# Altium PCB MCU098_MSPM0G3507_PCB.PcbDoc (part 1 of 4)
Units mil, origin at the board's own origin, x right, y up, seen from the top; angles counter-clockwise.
Board outline 2310.03 x 4205.03 mil, 4 copper layers (Top Layer, VCC Layer, GND Layer, Bottom Layer), stack 62.4 mil thick; 260 components, 182 nets, 835 pads, 237 vias.
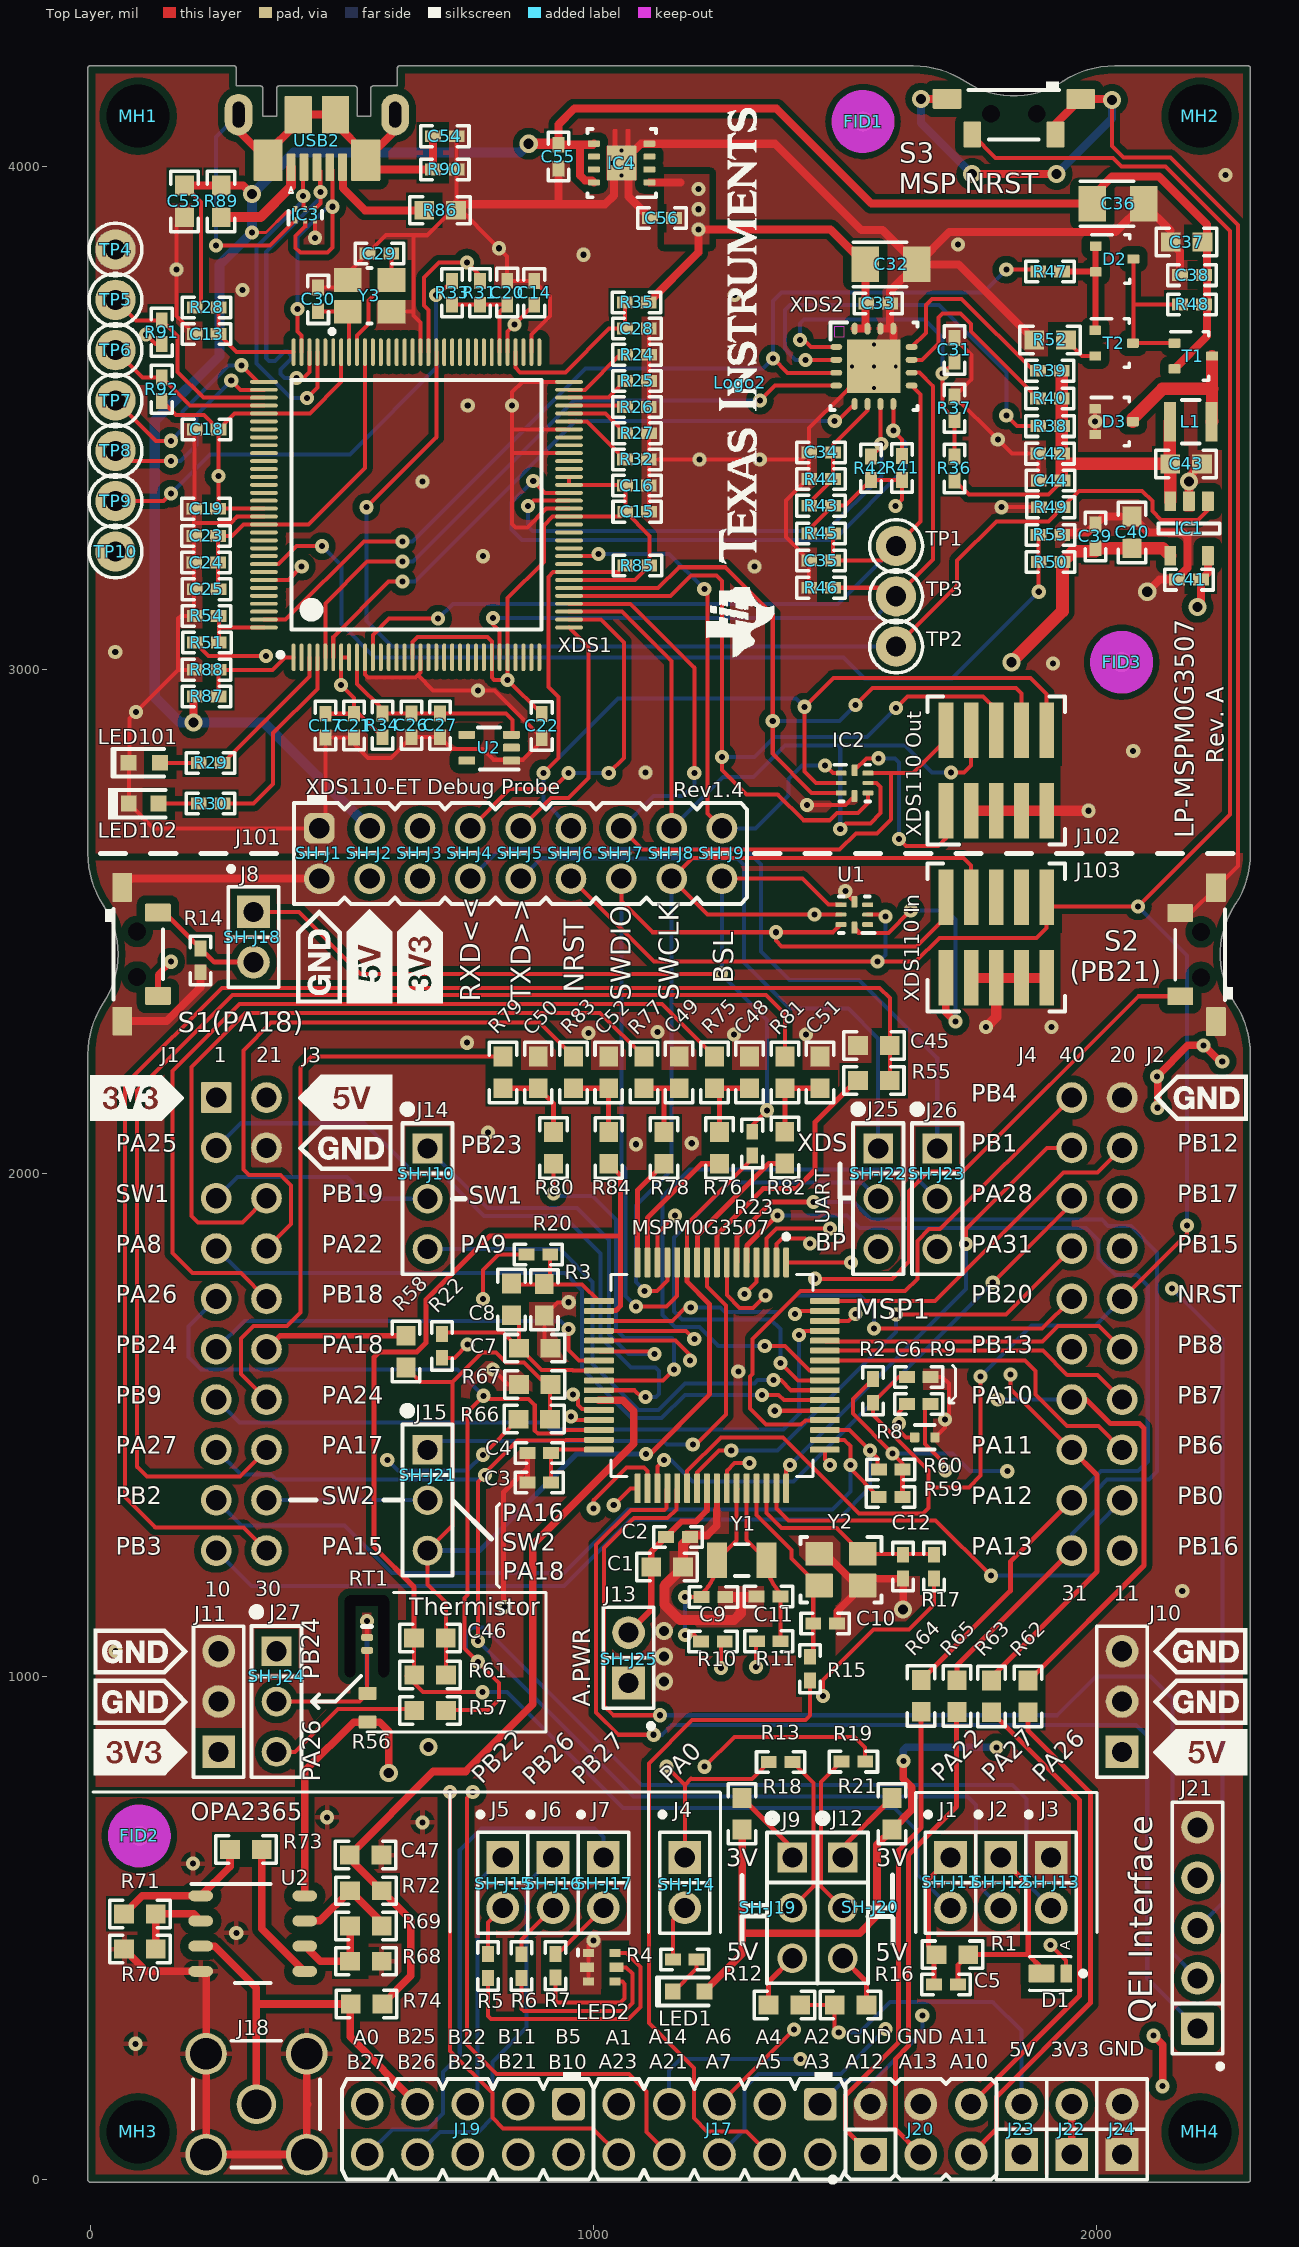
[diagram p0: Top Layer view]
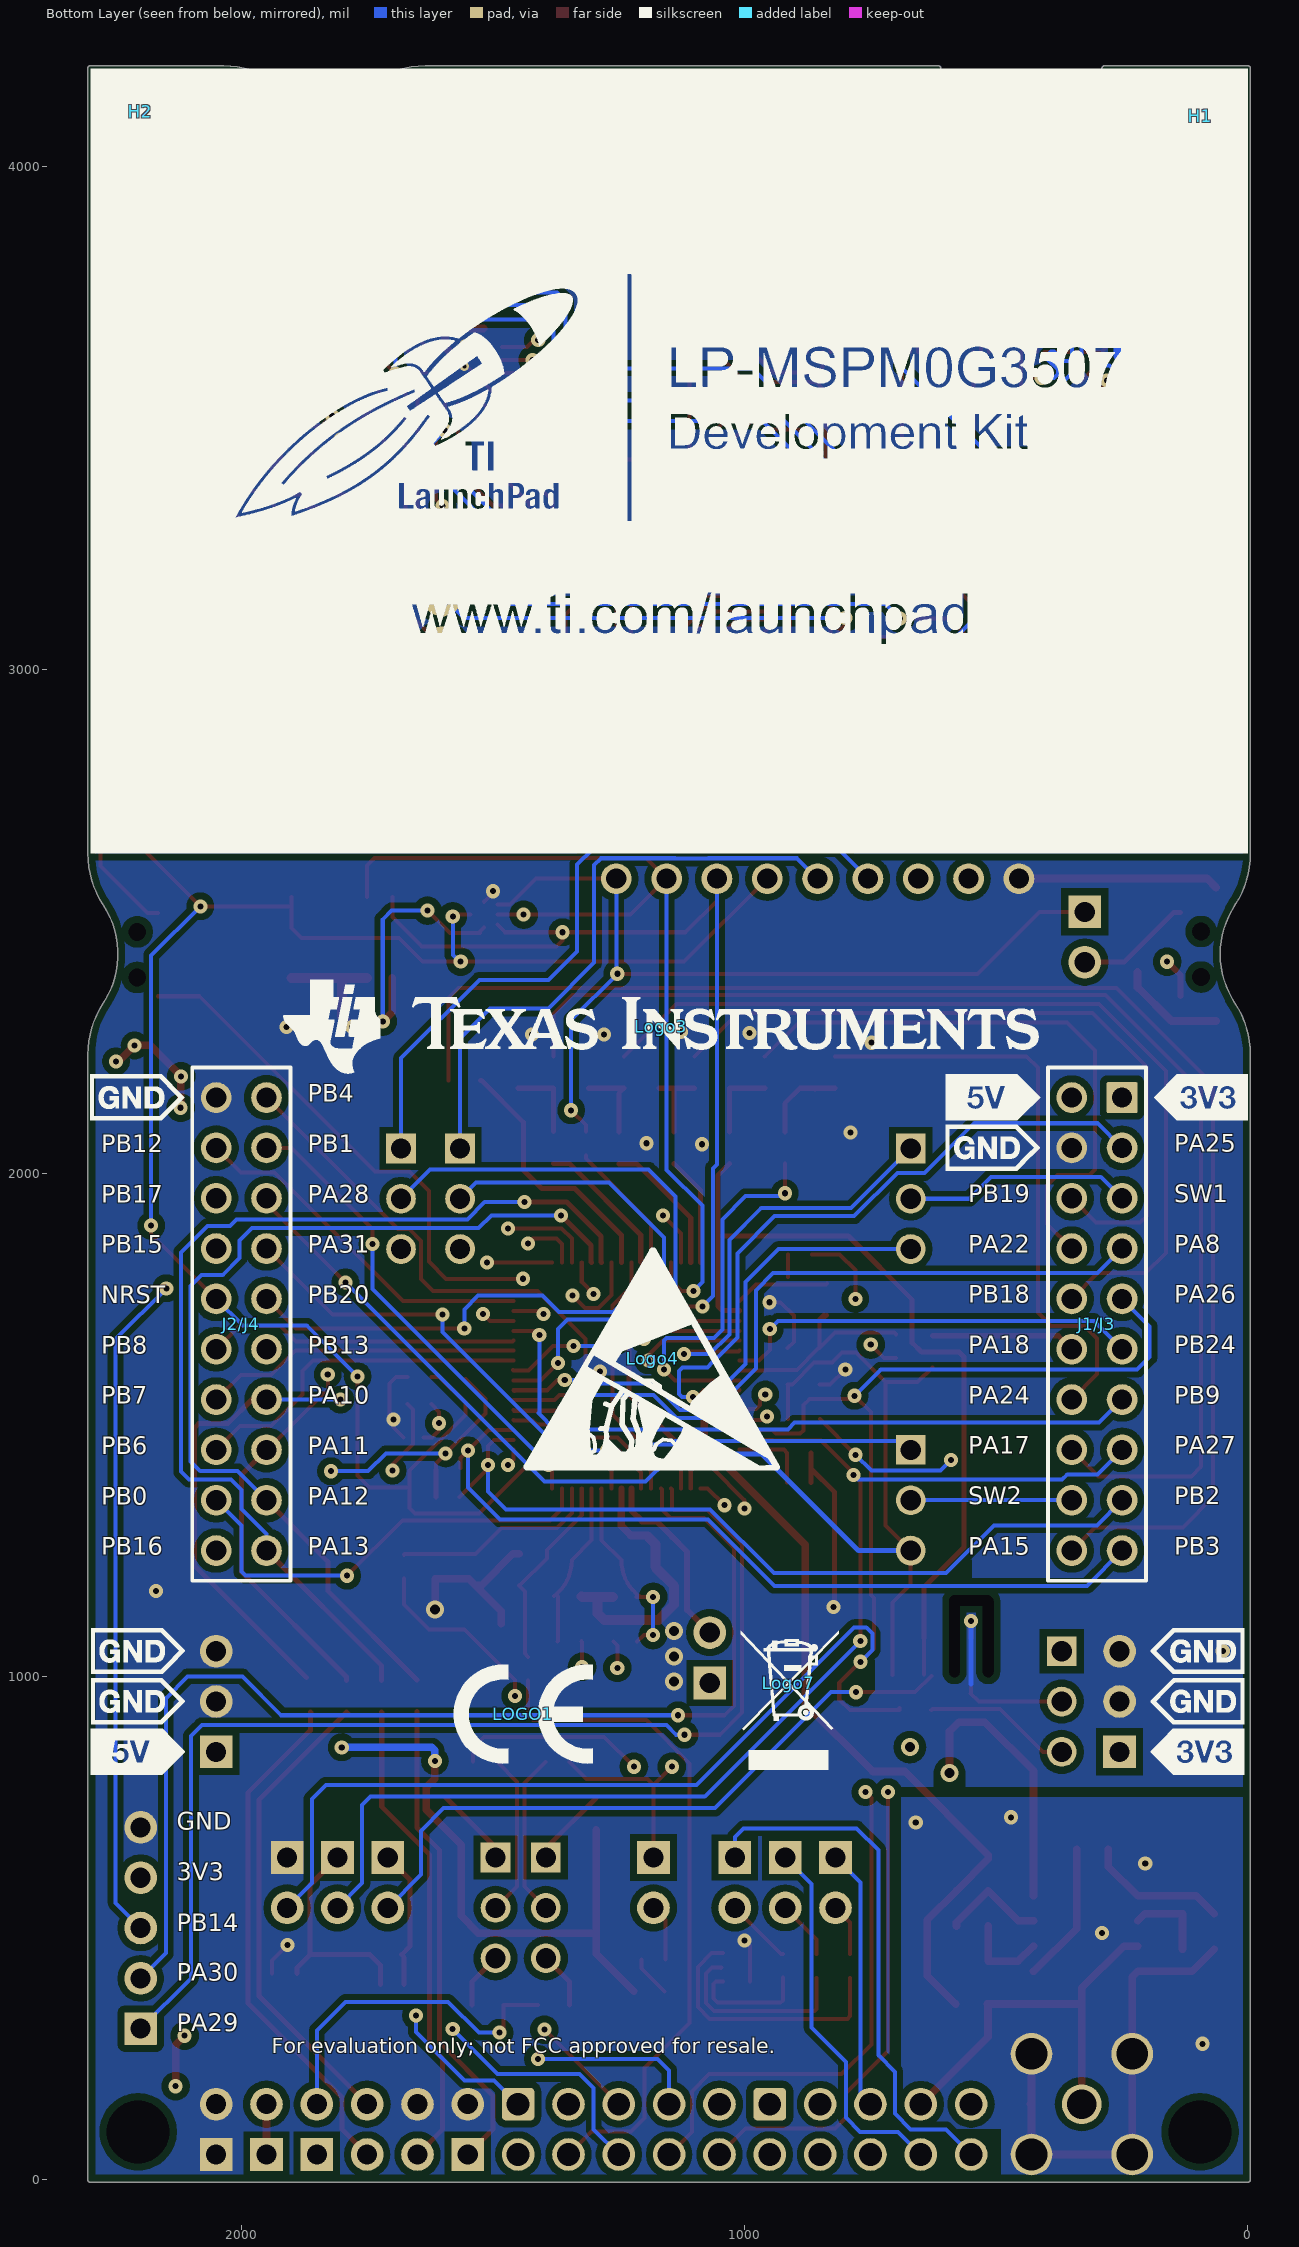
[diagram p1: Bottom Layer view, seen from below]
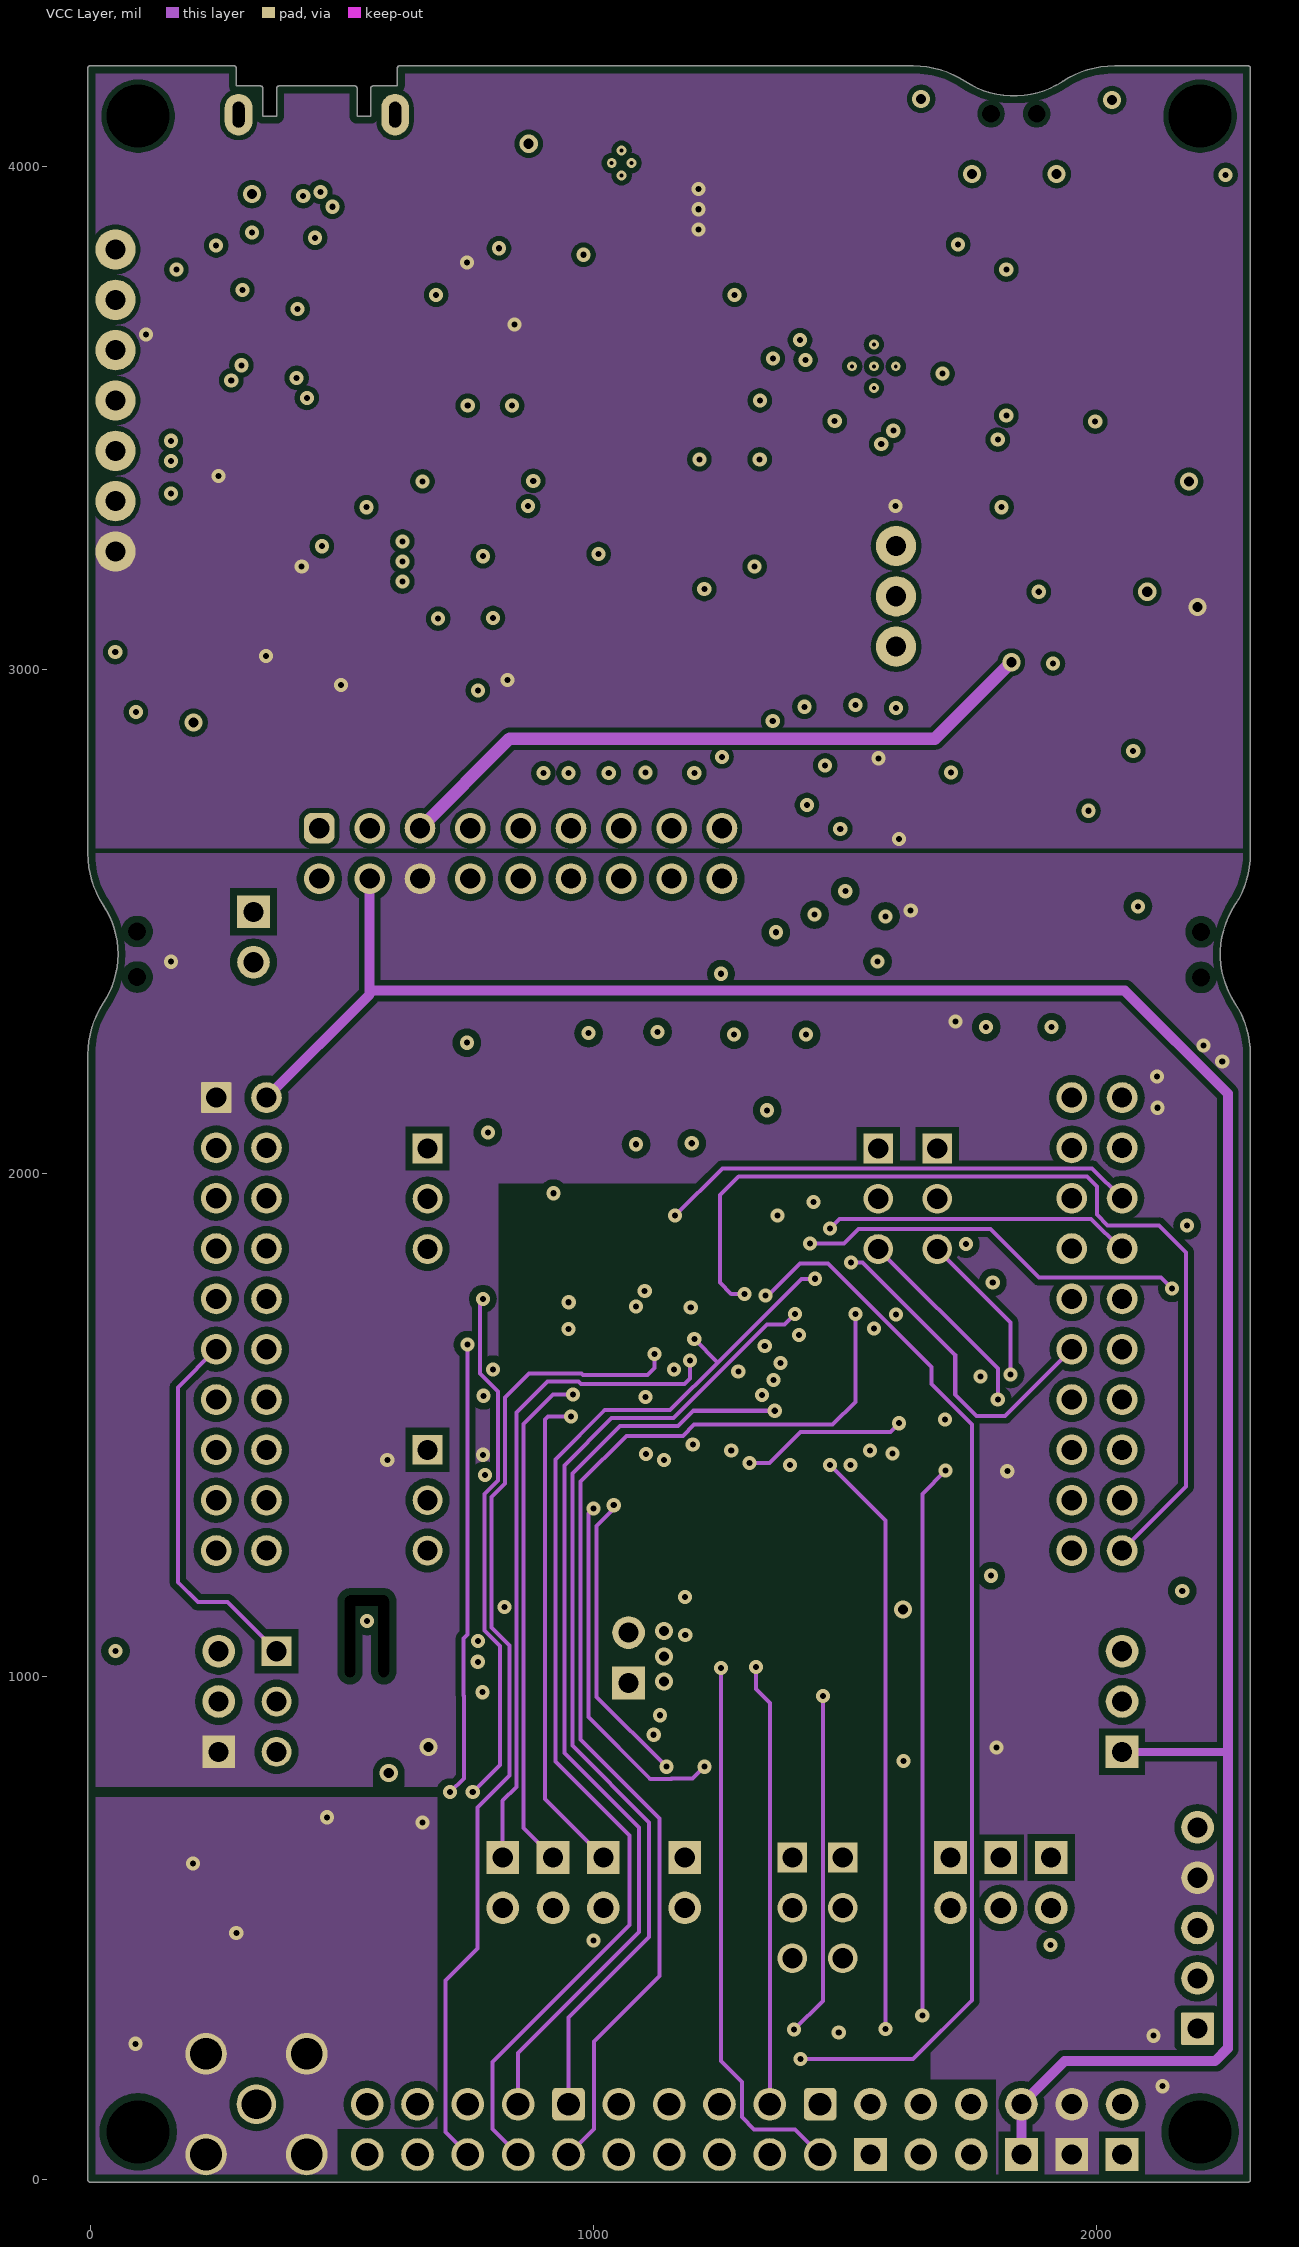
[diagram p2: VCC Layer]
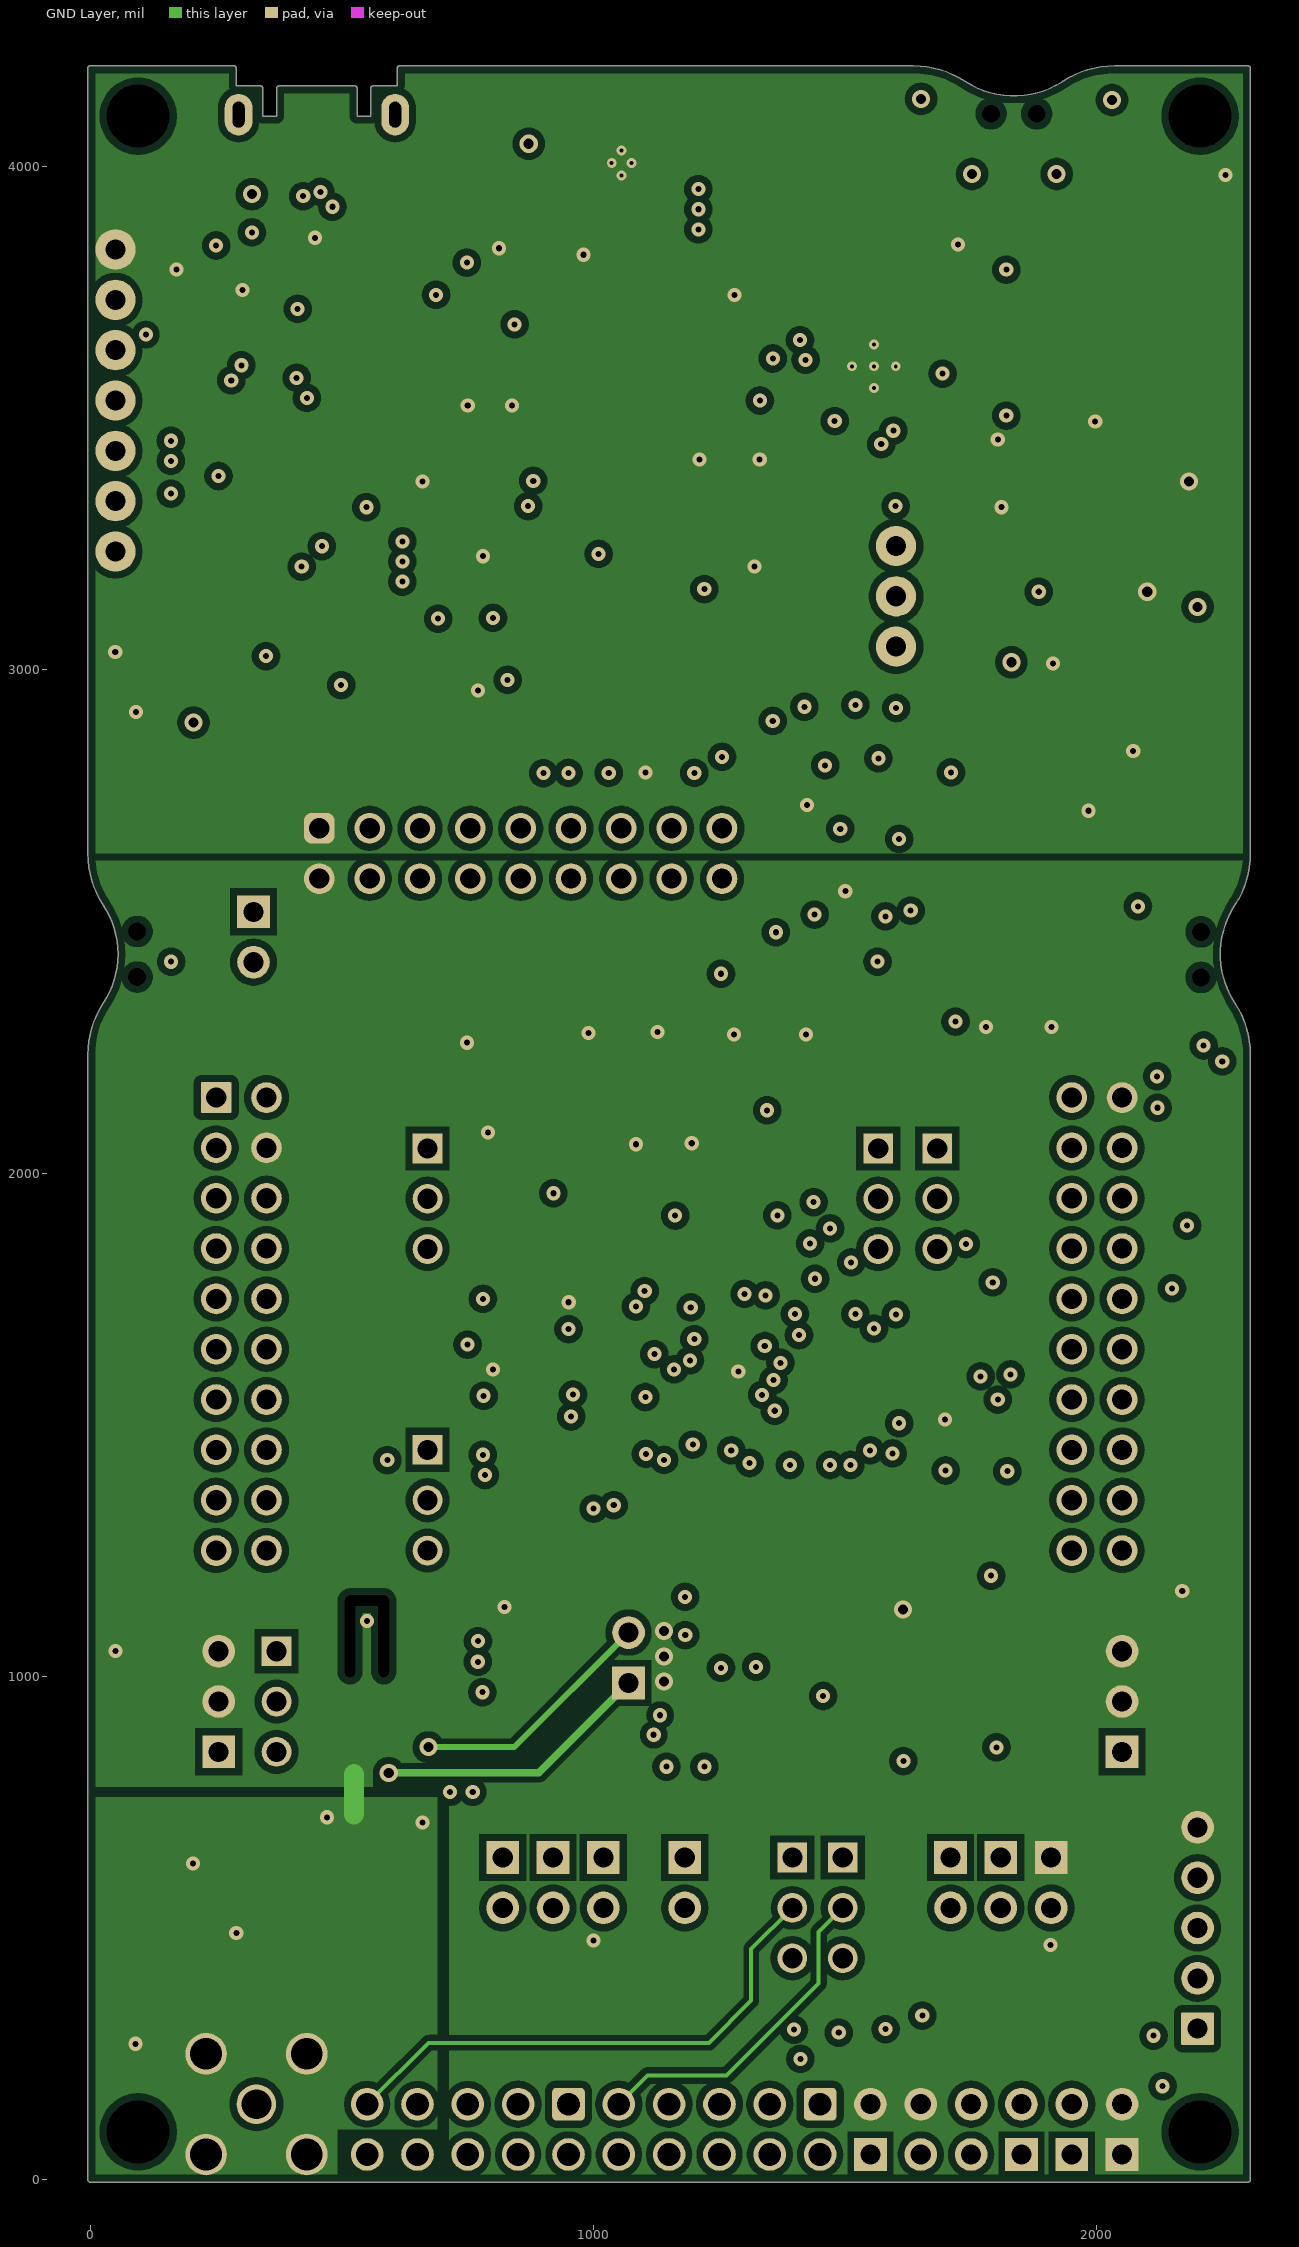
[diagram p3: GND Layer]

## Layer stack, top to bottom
Top Solder: solder mask 0.9843, SM-004, Dk 4
Top Layer: signal copper 1.4
Dielectric 2: core 8.4, FR-4, Dk 4.2
VCC Layer: signal copper 1.4
Dielectric1: prepreg 40, FR-4, Dk 4.2
GND Layer: signal copper 1.4
Dielectric 3: core 8.4, FR-4, Dk 4.2
Bottom Layer: signal copper 1.4
Bottom Solder: solder mask 0.9843, SM-004, Dk 4

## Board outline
-5.01,0 -5.01,2235 cw(c181.67,2235) 25.81,2337.76 ccw(c-121.67,2435) 25.83,2337.79 ccw(c-121.67,2435) 54.99,2435 ccw(c-121.67,2435) 25.88,2532.14 cw(c30,2535) 25.81,2532.24 cw(c181.67,2635) -5.01,2635 -5.01,4195 cw(c0,4195) 0,4200.02 285,4200.02 cw(c285,4195) 290.02,4195 290.02,4160.02 338,4160.02 cw(c338,4155) 343.02,4155 343.02,4100.02 369.99,4100.02 369.99,4155 cw(c375,4155) 375,4160.02 525,4160.02 cw(c525,4155) 530.02,4155 530.02,4100.02 556.99,4100.02 556.99,4155 cw(c562,4155) 562,4160.02 609.99,4160.02 609.99,4195 cw(c615,4195) 615,4200.02 1635,4200.02 cw(c1635,4013.33) 1737.76,4169.19 ccw(c1835,4316.67) 1737.79,4169.17 ccw(c1835,4316.67) 1932.14,4169.12 ccw(c1835,4316.67) 1932.24,4169.18 1932.24,4169.19 cw(c2035,4013.33) 2035,4200.02 2300,4200.02 cw(c2300,4195) 2305.02,4195 2305.02,2635 cw(c2118.33,2635) 2274.19,2532.24 cw(c2270,2535) 2274.17,2532.21 cw(c2421.67,2435) 2274.19,2532.24 2274.17,2532.21 ccw(c2421.67,2435) 2274.12,2337.86 cw(c2270,2335) 2274.19,2337.76 cw(c2118.33,2235) 2305.02,2235 2305.02,0.03 cw(c2300,0) 2305.02,0 2305.02,2235 2305.02,0.03 2305.02,0 cw(c2300,0) 2300,-5.01 0,-5.01 cw(c0,0)

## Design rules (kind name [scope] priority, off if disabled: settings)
AcuteAngle [All] p1: minimum=4.50000000000000E+0001 checktracksonly=FALSE
AssemblyTestPointUsage [All] p1: valid=2
BoardOutlineClearance BoardOutlineClearance_MountingHoles [OnCopper and InComponentClass('Mounting Holes')] p1: gap=15 ignorepadtopadclearanceinfootprint=FALSE
BoardOutlineClearance BoardOutlineClearance_Poly [OnCopper and IsPoly] p2: gap=15 ignorepadtopadclearanceinfootprint=FALSE
BoardOutlineClearance [OnCopper and Not InComponentClass('Logo') and not InComponentClass('FiducialMark') and not InRegion(1000,500,4000,800) and not InPoly] p3: gap=10 ignorepadtopadclearanceinfootprint=FALSE
Clearance SMD [InNamedPolygon('GND_LAYER_GND_P-001')] p1: gap=10 ignorepadtopadclearanceinfootprint=FALSE except(0: Arc-Hole Track-Hole SMDPad-Hole THPad-Hole Via-Hole Fill-Hole Poly-Hole Region-Hole Text-Hole; 20: SMDPad-SMDPad SMDPad-THPad SMDPad-Via SMDPad-Fill SMDPad-Poly SMDPad-Region SMDPad-Text)
Clearance Clearance_FiducialMark [IsKeepOut and InComponentClass('FiducialMark') vs IsPad and InComponentClass('FiducialMark')] p2: gap=0 ignorepadtopadclearanceinfootprint=FALSE
Clearance Clearance_Keepouts [((IsTrack Or IsArc) And Not InPoly) And IsFree and IsKeepOut vs ((IsTrack Or IsArc) And Not InPoly) And IsFree and IsKeepOut] p3: gap=0 ignorepadtopadclearanceinfootprint=FALSE
Clearance Clearance_Poly [InPolygon] p4: gap=14 ignorepadtopadclearanceinfootprint=FALSE except(0: Arc-Hole Track-Hole SMDPad-Hole THPad-Hole Via-Hole Fill-Hole Poly-Hole Region-Hole Text-Hole; 12: Arc-Fill Arc-Poly Arc-Region Track-Fill Track-Poly Track-Region; 15: THPad-THPad; 17: SMDPad-Fill SMDPad-Poly SMDPad-Region)
Clearance [All] p5: gap=6 ignorepadtopadclearanceinfootprint=FALSE
ComponentClearance ComponentClearance_Standoffs [HasFootprint('KY_MAE-10') vs HasFootprint('NPTH125mil')] p1: gap=0 collisioncheckmode=3 verticalgap=0 showdistances=FALSE
ComponentClearance ComponentClearance_2PinHeaders [HasFootprint('TSW-102-07-G-S') vs HasFootprint('TSW-102-07-G-S')] p2: gap=0 collisioncheckmode=3 verticalgap=0 showdistances=FALSE
ComponentClearance ComponentClearance_TestPoint [HasFootprint('Keystone5001') vs HasFootprint('Keystone5001')] p3: gap=0 collisioncheckmode=3 verticalgap=0 showdistances=FALSE
ComponentClearance ComponentClearance_MountingHoles_FiducialMarks [InComponentClass('Mounting Holes') vs InComponentClass('FiducialMark')] p4: gap=0 collisioncheckmode=3 verticalgap=0 showdistances=FALSE
ComponentClearance ComponentClearance_ShuntToShunt [InComponentClass('Shunt') vs InComponentClass('Shunt')] p5: gap=0 collisioncheckmode=3 verticalgap=0 showdistances=FALSE
ComponentClearance ComponentClearance_Shunt [InComponentClass('Header') vs InComponentClass('Shunt')] p6: gap=0 collisioncheckmode=3 verticalgap=0 showdistances=FALSE
ComponentClearance ComponentClearance_Logo [InComponentClass('Logo')] p7: gap=0 collisioncheckmode=3 verticalgap=0 showdistances=FALSE
ComponentClearance ComponentClearance_ScrewToNut [(HasFootprint('NY PMS 440 0025 PH')) vs (HasFootprint('Keystone_1902C'))] p8: gap=5 collisioncheckmode=3 verticalgap=10 showdistances=FALSE
ComponentClearance ComponentClearance_MountingHoles [InComponentClass('Mounting Holes')] p9: gap=250 collisioncheckmode=3 verticalgap=100000 showdistances=FALSE
ComponentClearance ComponentClearance_SmallPassives [HasFootprint('0201*') or HasFootprint('0402*') or HasFootprint('0508') or HasFootprint('0603*') or HasFootprint('0612') or HasFootprint('0805*') or HasFootprint('0815*') or HasFootprint('0830*') or HasFootprint('1206*') or HasFootprint('1210*') or HasFootprint('1808*') or HasFootprint('1812*') or HasFootprint('1825*') or HasFootprint('2010*') or HasFootprint('2220*') or HasFootprint('2225*') or HasFootprint('2512*') or HasFootprint('2728*') or HasFootprint('3518*') vs HasFootprint('0201*') or HasFootprint('0402*') or HasFootprint('0508') or HasFootprint('0603*') or HasFootprint('0612') or HasFootprint('0805*') or HasFootprint('0815*') or HasFootprint('0830*') or HasFootprint('1206*') or HasFootprint('1210*') or HasFootprint('1808*') or HasFootprint('1812*') or HasFootprint('1825*') or HasFootprint('2010*') or HasFootprint('2220*') or HasFootprint('2225*') or HasFootprint('2512*') or HasFootprint('2728*') or HasFootprint('3518*')] p10: gap=0 collisioncheckmode=3 verticalgap=0 showdistances=FALSE
ComponentClearance ComponentClearance_THtoSMT [IsThruComponent vs IsSMTComponent] p11: gap=0 collisioncheckmode=3 verticalgap=0 showdistances=FALSE
ComponentClearance ComponentClearance_THtoTH [IsThruComponent vs IsThruComponent] p12: gap=0 collisioncheckmode=3 verticalgap=0 showdistances=FALSE
ComponentClearance [All] p13: gap=0 collisioncheckmode=3 verticalgap=0 showdistances=FALSE
DiffPairsRouting [All] p1: maxlimit=100 minlimit=10 mostfreqgap=10 toplayer_minwidth=15 toplayer_maxwidth=15 toplayer_prefwidth=15 midlayer1_minwidth=15 midlayer1_maxwidth=15 midlayer1_prefwidth=15 midlayer2_minwidth=15 midlayer2_maxwidth=15 midlayer2_prefwidth=15 bottomlayer_minwidth=15 bottomlayer_maxwidth=15 bottomlayer_prefwidth=15 maxuncoupledlength=1000
FabricationTestPointUsage TestPointUsage [All] p1: valid=2 allowmultiple=FALSE
FabricationTestpoint Testpoint [All] p1: side=3 testpointundercomponent=TRUE minsize=40 maxsize=100 preferedsize=60 minholesize=0 maxholesize=40 preferedholesize=32 testpointgrid=1 allowsidetop=TRUE allowsidebottom=TRUE usegrid=TRUE gridtolerance=0.01
FanoutControl Fanout_LCC [IsLCC] p1: bgadir=Out bgaviamode=Centered fanoutstyle=Auto fanoutdirection=Alternating viagrid=1 // Fanout_LCC (Default Rule)
FanoutControl Fanout_BGA [IsBGA] p2: bgadir=Out bgaviamode=Centered fanoutstyle=Auto fanoutdirection=Alternating viagrid=1 // Fanout_BGA (Default Rule)
FanoutControl Fanout_Default [All] p4: bgadir=Out bgaviamode=Centered fanoutstyle=Auto fanoutdirection=Alternating viagrid=1 // Fanout_Default (Default Rule)
FanoutControl Fanout_Small [(CompPinCount < 5)] p5: bgadir=Out bgaviamode=Centered fanoutstyle=Auto fanoutdirection=OutThenIn viagrid=1 // Fanout_Small (Default Rule)
HoleSize [All] p1: absolutevalues=TRUE maxlimit=251 minlimit=7.87 maxpercent=80.000 minpercent=20.000
MinimumAnnularRing MinimumAnnularRing_ThermalPadVias [IsVia and InAnyComponent] p1: minimumring=5.91
MinimumAnnularRing [All] p2: minimumring=6
MinimumSolderMaskSliver MinimumSolderMaskSliver_Logo [InComponentClass('Logo') vs InComponentClass('Logo')] p1: minsoldermaskwidth=0.7
MinimumSolderMaskSliver [All] p2: minsoldermaskwidth=3.94
PlaneClearance [All] p1: clearance=10
PlaneConnect [All] p1: planeconnectstyle=Relief reliefexpansion=10 reliefentries=4 reliefconductorwidth=10 reliefairgap=10
PolygonConnect PolygonConnect_14 [All vs IsNamedPolygon('GND_LAYER_GND_P-001')] p1: connectstyle=Direct reliefconductorwidth=10 reliefentries=4 polygonreliefangle="90 Angle" airgapwidth=10
PolygonConnect PolygonConnect_13 [All vs IsNamedPolygon('BOTTOM_LAYER_GND_P036')] p2: connectstyle=Direct reliefconductorwidth=10 reliefentries=4 polygonreliefangle="90 Angle" airgapwidth=10
PolygonConnect PolygonConnect_12 [All vs IsNamedPolygon('TOP_LAYER_GND_P034')] p3: connectstyle=Direct reliefconductorwidth=10 reliefentries=4 polygonreliefangle="90 Angle" airgapwidth=10
PolygonConnect PolygonConnect_11 [All vs IsNamedPolygon('VCC_LAYER_3V3_P032')] p4: connectstyle=Direct reliefconductorwidth=10 reliefentries=4 polygonreliefangle="90 Angle" airgapwidth=10
PolygonConnect PolygonConnect_10 [All vs IsNamedPolygon('GND_LAYER_GND_P030')] p5: connectstyle=Direct reliefconductorwidth=10 reliefentries=4 polygonreliefangle="90 Angle" airgapwidth=10
PolygonConnect PolygonConnect_9 [All vs IsNamedPolygon('BOTTOM_LAYER_GND_P028')] p6: connectstyle=Direct reliefconductorwidth=10 reliefentries=4 polygonreliefangle="90 Angle" airgapwidth=10
PolygonConnect PolygonConnect_8 [All vs IsNamedPolygon('GND_LAYER_GND_P026')] p7: connectstyle=Direct reliefconductorwidth=10 reliefentries=4 polygonreliefangle="90 Angle" airgapwidth=10
PolygonConnect PolygonConnect_7 [All vs IsNamedPolygon('VCC_LAYER_GND_P024')] p8: connectstyle=Direct reliefconductorwidth=10 reliefentries=4 polygonreliefangle="90 Angle" airgapwidth=10
PolygonConnect PolygonConnect_6 [All vs IsNamedPolygon('TOP_LAYER_GND_P022')] p9: connectstyle=Relief reliefconductorwidth=10 reliefentries=4 polygonreliefangle="90 Angle" airgapwidth=10
PolygonConnect PolygonConnect_5 [All vs IsNamedPolygon('BOTTOM_LAYER_XDS_GND_P014')] p10: connectstyle=Direct reliefconductorwidth=10 reliefentries=4 polygonreliefangle="90 Angle" airgapwidth=10
PolygonConnect PolygonConnect_4 [All vs IsNamedPolygon('TOP_LAYER_XDS_GND_P010')] p11: connectstyle=Direct reliefconductorwidth=10 reliefentries=4 polygonreliefangle="90 Angle" airgapwidth=10
PolygonConnect PolygonConnect_3 [All vs IsNamedPolygon('GND_LAYER_XDS_GND_P008')] p12: connectstyle=Direct reliefconductorwidth=10 reliefentries=4 polygonreliefangle="90 Angle" airgapwidth=10
PolygonConnect PolygonConnect_2 [All vs IsNamedPolygon('TOP_LAYER_XDS_VCC_P004')] p13: connectstyle=Direct reliefconductorwidth=10 reliefentries=4 polygonreliefangle="90 Angle" airgapwidth=10
RoutingVias ThermalPadVias [IsVia and InAnyComponent] p1: holewidth=7.87 width=19.68 viastyle="Through Hole" minholewidth=7.87 minwidth=19.68 maxholewidth=16 maxwidth=30
RoutingVias [All] p2: holewidth=12 width=28 viastyle="Through Hole" minholewidth=7.87 minwidth=26 maxholewidth=40 maxwidth=65
SilkToBoardRegionClearance [Not ((IsComment or IsDesignator) And (Hide <> 'False')) and not InRegion(1000,500,4000,800)] p1:
SilkToSilkClearance SilkToSilkClearance_Pb-FreeLogo [(HasFootprint('Pb-Free_Overlay_Medium') OR HasFootprint('Pb-Free_Overlay_Small')) vs (HasFootprint('Pb-Free_Overlay_Medium') OR HasFootprint('Pb-Free_Overlay_Small'))] p1: silktosilkclearance=0
SilkToSilkClearance [All] p2: silktosilkclearance=0
SilkToSolderMaskClearance SilkToComponentPadClearance [(IsPad or IsFill or IsRegion) and InAnycomponent] p1: minsilkscreentomaskgap=0 clearancetoexposedcopper=TRUE
SilkToSolderMaskClearance "Silk to Solder Mask Opening" [All] p2: minsilkscreentomaskgap=0 clearancetoexposedcopper=FALSE
SolderMaskExpansion SolderMaskExpansion_via [isvia] p1: expansion=-17
SolderMaskExpansion [All] p2: expansion=1.97
Width [All] p1: maxlimit=100 minlimit=6 preferedwidth=10 checkconnectedcopper=TRUE
14 further rules are at their usual default settings.

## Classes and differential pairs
component class MCU098_07_Hardware: "30N.C. ROUTE" !PCB FID1 FID2 FID3 H1 H2 LOGO1 Logo2 Logo3 Logo4 Logo6 Logo7 MH1 MH2 MH3 MH4 SH-J1 SH-J2 SH-J3 SH-J4 SH-J5 SH-J6 SH-J7 SH-J8 SH-J9 SH-J10 SH-J11 SH-J12 SH-J13 SH-J14 SH-J15 SH-J16 SH-J17 SH-J18 SH-J19 SH-J20 SH-J21 SH-J22 SH-J23 SH-J24 SH-J25 SH-J101A SH-J101B SH-J101C SH-J101D SH-J101E SH-J101F SH-J101G SH-J101H SH-J101I SH-J101J USB1 ZZ1 ZZ2 ZZ3 ZZ4
component class MCU098_06_XDS110-ET_USB_Power: "30N.C. ROUTE" C53 C54 C55 C56 IC3 IC4 R86 R87 R88 R89 R90 R91 R92 TP4 TP5 TP6 TP7 TP8 TP9 TP10 USB2
component class MCU098_05_XDS110_Target_Interface: "30N.C. ROUTE" IC2 J101 J102 J103 R85 U1
component class MCU098_04_XDS110-ET_EnergyTrace: "30N.C. ROUTE" C31 C32 C33 C34 C35 C36 C37 C38 C39 C40 C41 C42 C43 C44 D2 D3 IC1 L1 R36 R37 R38 R39 R40 R41 R42 R43 R44 R45 R46 R47 R48 R49 R50 R51 R52 R53 R54 T1 T2 XDS2
component class MCU098_03_XDS110_Debug_Probe: "30N.C. ROUTE" C13 C14 C15 C16 C17 C18 C19 C20 C21 C22 C23 C24 C25 C26 C27 C28 C29 C30 LED101 LED102 R24 R25 R26 R27 R28 R29 R30 R31 R32 R33 R34 R35 TP1 TP2 TP3 U2 XDS1 Y3
component class MCU098_02_BoosterPack_Connectors: "30N.C. ROUTE" C45 C46 C47 C48 C49 C50 C51 C52 J1/J3 J2/J4 J14 J15 J17 J18 J19 J20 J21 J22 J23 J24 J27 R55 R56 R57 R58 R59 R60 R61 R62 R63 R64 R65 R66 R67 R68 R69 R70 R71 R72 R73 R74 R75 R76 R77 R78 R79 R80 R81 R82 R83 R84 RT1 U2
component class MCU098_01_MSPM0G3507_Target_Device: "30N.C. ROUTE" C1 C2 C3 C4 C5 C6 C7 C8 C9 C10 C11 C12 D1 J1 J2 J3 J4 J5 J6 J7 J8 J9 J10 J11 J12 J13 J25 J26 LED1 LED2 MSP1 R1 R2 R3 R4 R5 R6 R7 R8 R9 R10 R11 R12 R13 R14 R15 R16 R17 R18 R19 R20 R21 R22 R23 S1 S2 S3 Y1 Y2
component class FiducialMark: "30N.C. ROUTE" FID1 FID2 FID3
component class AssemblyNote: "30N.C. ROUTE" ZZ2 ZZ3 ZZ4 ZZ6
component class Logo: "30N.C. ROUTE" Logo2 Logo3
component class Header: "30N.C. ROUTE" J1 J2 J3 J4 J5 J6 J7 J8 J9 J10 J11 J12 J13 J14 J15 J17 J19 J20 J21 J22 J23 J24 J25 J26 J27 J101
component class Shunt: SH-J1 SH-J2 SH-J3 SH-J4 SH-J5 SH-J6 SH-J7 SH-J8 SH-J9 SH-J10 SH-J11 SH-J12 SH-J13 SH-J14 SH-J15 SH-J16 SH-J17 SH-J18 SH-J19 SH-J20 SH-J21 SH-J22 SH-J23 SH-J24 SH-J25

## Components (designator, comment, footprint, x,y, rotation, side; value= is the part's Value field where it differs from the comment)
C1 "GRM188R60J106ME84" 0603 1146,1217 r0 top value=10uF
C2 "GRM155R61H104ME14D" 0402 1167.65,1277 r0 top value=0.1uF
C3 "GRM155R60J474KE19D" 0402 892,1385.27 r180 top value=0.47uF
C4 "GRM155R61H104ME14D" 0402 892,1444 r180 top value=0.1uF
C5 "GRM1555C1E470JA01D" 0402 1700,387.54 r0 top value=47pF
C6 "GRM155R61C103KA01D" 0402 1646,1595 r0 top value=0.01uF
C7 "C1608X5R1E105K080AC" 0603 883,1652 r0 top value=1uF
C8 "C1608X5R1E105K080AC" 0603 836.63,1749 r90 top value=1uF
C9 "GRM1555C1H220JA01D" 0402 1238,1158 r180 top value=22pF
C10 "GRM1555C1H220JA01D" 0402 1460,1105 r180 top value=22pF
C11 "GRM1555C1H220JA01D" 0402 1347.34,1158.65 r0 top value=22pF
C12 "GRM1555C1H220JA01D" 0402 1615,1218 r90 top value=22pF
C13 "GRM155R70J104KA01D" 0402 231,3667 r180 top value=0.1uF
C14 "GRM155R71E103KA01D" 0402 882,3749 r90 top value=0.01uF
C15 "GRM155R71E103KA01D" 0402 1086.5,3314 r0 top value=0.01uF
C16 "GRM155R71E103KA01D" 0402 1086,3366 r0 top value=0.01uF
C17 "GRM155R70J104KA01D" 0402 467.5,2889 r270 top value=0.1uF
C18 "GRM155R70J104KA01D" 0402 231,3477.61 r180 top value=0.1uF
C19 "C1005X5R1E105K050BC" 0402 230,3320 r180 top value=1uF
C20 "GRM155R70J104KA01D" 0402 828.45,3749.33 r90 top value=0.1uF
C21 "C1005X5R1E105K050BC" 0402 524,2889 r270 top value=1uF
C22 "GRM155R71E103KA01D" 0402 897,2888.38 r270 top value=0.01uF
C23 "GRM155R60J225KE95D" 0402 230,3266 r180 top value=2.2uF
C24 "GRM155R70J104KA01D" 0402 230,3213 r180 top value=0.1uF
C25 "C1005X5R1E105K050BC" 0402 231,3160 r180 top value=1uF
C26 "GRM155R71E103KA01D" 0402 638,2889.63 r270 top value=0.01uF
C27 "GRM155R70J104KA01D" 0402 695,2889.63 r270 top value=0.1uF
C28 "GRM155R70J104KA01D" 0402 1086,3678 r0 top value=0.1uF
C29 "GRM1555C1H120JA01D" 0402 574.38,3826.97 r180 top value=12pF
C30 "GRM1555C1H120JA01D" 0402 452.72,3736 r90 top value=12pF
C31 "GRM1555C1H330JA01D" 0402 1717,3635.62 r90 top value=33pF
C32 "TAJA475K016RNJ" 3216-18 1591.02,3805.58 r0 top value=4.7uF
C33 "GRM155R70J104KA01D" 0402 1565.38,3728 r0 top value=0.1uF
C34 "GRM1555C1H330JA01D" 0402 1452,3432 r180 top value=33pF
C35 "GCM155R71H102KA37D" 0402 1452,3217 r180 top value=1000pF
C36 "TAJA475K016RNJ" 3216-18 2042,3926 r0 top value=4.7uF
C37 "GRM188R61C475KAAJ" 0603 2178,3849.87 r0 top value=4.7uF
C38 "GRM155R70J104KA01D" 0402 2189,3784 r180 top value=0.1uF
C39 "GRM155R70J104KA01D" 0402 1997,3265 r90 top value=0.1uF
C40 "GRM188R60J476ME15D" 0603 2070,3273 r90 top value=47uF
C41 "GRM155R71C224KA12D" 0402 2183,3179 r180 top value=0.22uF
C42 "GRM155R71C224KA12D" 0402 1907,3429.35 r180 top value=0.22uF
C43 "GRM188R61C475KAAJ" 0603 2177,3409 r180 top value=4.7uF
C44 "GRM155R70J104KA01D" 0402 1908,3376 r180 top value=0.1uF
C45 "C0603C225K8PACTU" 0603 1557.03,2253.53 r180 top value=2.2uF
C46 "C0603C225K8PACTU" 0603 674.76,1076.5 r180 top value=2.2uF
C47 "C0603C820K5GACTU" 0603 547.01,644.99 r0 top value=82pF
C48 "C0603C225K8PACTU" 0603 1310,2200 r90 top value=2.2uF
C49 "C0603C225K8PACTU" 0603 1170,2200 r90 top value=2.2uF
C50 "C0603C225K8PACTU" 0603 890,2200 r90 top value=2.2uF
C51 "C0603C225K8PACTU" 0603 1450,2200 r90 top value=2.2uF
C52 "C0603C225K8PACTU" 0603 1030,2200 r90 top value=2.2uF
C53 "C0603C225K8PACTU" 0603 187,3930.72 r270 top value=2.2uF
C54 "GRM155R71H332KA01D" 0402 704.38,4060 r0 top value=3300pF
C55 "C1005X5R1E105K050BC" 0402 930,4019.58 r270 top value=1uF
C56 "GRM155R60J225KE95D" 0402 1135.73,3897.58 r180 top value=2.2uF
D1 "VEMD4110X01" FP-VEMD4110X01_0805-MFG 1907.5,409.52 r90 top
D2 "BAS40-05W,115" SOT-323 2035,3816.13 r0 top value=40V
D3 "BAS40-05W,115" SOT-323 2034,3493 r0 top value=40V
FID1 "Fiducial" Fiducial10-30 1535.26,4089.22 r0 top
FID2 "Fiducial" Fiducial10-30 97.5,683 r90 top
FID3 "Fiducial" Fiducial10-30 2049.12,3015 r90 top
H1 "MAE-10" KY_MAE-10 95,4100 r180 bottom
H2 "MAE-10" KY_MAE-10 2201,4108.78 r180 bottom
IC1 "TPS2102DBVR" DBV0005A_N 2183,3280.87 r270 top
IC2 "TPD6E004RSER" RSE0008A 1518.56,2774.88 r0 top
IC3 "TPD4E004DRYR" DRY0006A 427,3904 r90 top
IC4 "TPS73533DRBT" DRB0008A 1055.61,4006.78 r180 top
J1 "90120-0122" CONN_90120-0122 1709,590 r270 top
J1/J3 "SSQ-110-03-T-D" BoosterPack_40pin_J1J3 300,1700 r180 bottom locked
J2 "90120-0122" CONN_90120-0122 1809,590 r270 top
J2/J4 "SSQ-110-03-T-D" BoosterPack_40pin_J2J4 2000,1700 r180 bottom locked
J3 "90120-0122" CONN_90120-0122 1909,590 r270 top
J4 "90120-0122" CONN_90120-0122 1181.14,590 r270 top
J5 "90120-0122" CONN_90120-0122 819.38,590 r270 top
J6 "90120-0122" CONN_90120-0122 919.38,590 r270 top
J7 "90120-0122" CONN_90120-0122 1019.38,590 r270 top
J8 "90120-0122" CONN_90120-0122 324.12,2468.97 r270 top
J9 "PEC03SAAN" CONN_PEC03SAAN 1394.88,540 r270 top
J10 "PEC03SAAN" PEC03SAAN_Launchpad_5V0 2050,950 r90 top
J11 "PEC03SAAN" PEC03SAAN_Launchpad_3V3 255,950 r90 top
J12 "PEC03SAAN" CONN_PEC03SAAN 1494.88,540 r270 top
J13 "90120-0122" CONN_90120-0122 1069.38,1037 r90 top
J14 "PEC03SAAN" CONN_PEC03SAAN 670,1949 r270 top
J15 "PEC03SAAN" CONN_PEC03SAAN 670,1350 r270 top
J17 "61301021121" WURTH_61301021121 1250,100 r180 top
J18 "5-1814832-1" TE_5-1814832-1 330,150 r0 top
J19 "61301021121" WURTH_61301021121 750,100 r180 top
J20 "PBC03DAAN" Sullins_PBC03DAAN 1650,100 r90 top
J21 "HTSW-105-07-G-S" Samtec_HTSW-105-07-G-S 2200,500 r90 top net-tie
J22 "90120-0122" CONN_90120-0122 1950,100 r90 top
J23 "90120-0122" CONN_90120-0122 1850,100 r90 top
J24 "90120-0122" CONN_90120-0122 2050,100 r90 top
J25 "PEC03SAAN" CONN_PEC03SAAN 1565.39,1949 r270 top
J26 "PEC03SAAN" CONN_PEC03SAAN 1682.72,1949 r270 top
J27 "PEC03SAAN" CONN_PEC03SAAN 370,950 r270 top
J101 "PEC09DAAN" Sullins_PxC09DAAN 855,2635 r270 top
J102 "FTSH-105-01-L-DV-K" Samtec_FTSH-105-01-x-DV-K 1800,2800 r90 top
J103 "FTSH-105-01-L-DV-K" Samtec_FTSH-105-01-x-DV-K 1800,2468 r90 top
L1 "CBC2518T2R2M" CBC2518 2186.4,3493 r180 top value=2.2uH
LED1 "BR1111C-TR" 1111C_Red 1188.79,374 r180 top value=Red
LED2 "19-337/R6GHBHC-A01/2T" 19-337_RGB 1016,422 r0 top value=Rgb
LED101 "BR1111C-TR" 1111C_Red 107.12,2815.41 r180 top value=Red
LED102 "LTST-C190GKT" LED_LTST-C190 106,2734 r180 top value=Green
LOGO1 "CE Mark" CE_Mark_5mm 1440.03,925 r180 bottom
Logo2 "Texas Instruments" TI_Horizontal_Overlay_Small 1291,3570 r90 top
Logo3 "Texas Instruments" TI_Horizontal_Overlay_Medium 1166,2291 r180 bottom
Logo4 "ESD Susceptible" ESD_Overlay_Large 1182.65,1630.69 r180 bottom
Logo6 "FCC disclaimer" FCC_disclaimer 3226,1764 r0 bottom
Logo7 "WEEE logo" WEEE_Minimum 912.57,986.5 r180 bottom
MH1 "MTG_NoPads" NPTH125mil 95,4100 r0 top locked
MH2 "MTG_NoPads" NPTH125mil 2205,4100 r0 top locked
MH3 "MTG_NoPads" NPTH125mil 95,95 r0 top locked
MH4 "MTG_NoPads" NPTH125mil 2205,95 r0 top locked
MSP1 "MSPM0G3507SPM" PM0064A-MFG 1235,1598 r270 top (schematic designator U1)
R1 "CRCW06032M37FKEA" 0603 1713,447 r180 top value=2.37Meg
R2 "CRCW040247K0JNED" 0402 1555,1567.38 r90 top value=47k
R3 "RC0603JR-070RL" 0603 902,1748.34 r90 top value=0
R4 "CRCW0402470RJNED" 0402 1181,437.26 r0 top value=470
R5 "CRCW0402220RJNED" 0402 790.16,424.43 r270 top value=220
R6 "CRCW0402330RJNED" 0402 857,424.38 r270 top value=330
R7 "CRCW0402330RJNED" 0402 924,425 r270 top value=330
R8 "ERA-2AEB104X" FP-ERA-2AEB104X_0402-MFG 1658,1475 r0 top
R9 "RC0402JR-070RL" 0402 1646,1541 r180 top value=0
R10 "RC0402JR-070RL" 0402 1237,1069 r180 top value=0
R11 "RC0402JR-070RL" 0402 1348,1069.75 r0 top value=0
R12 "RC0603JR-074K7L" 0603 1379,347 r0 top value=4.7k
R13 "CRCW0402270RJNED" 0402 1371.62,830 r0 top value=270
R14 "CRCW040247K0JNED" 0402 219,2422.62 r90 top value=47k
R15 "RC0402JR-070RL" 0402 1430,1015.25 r90 top value=0
R16 "RC0603JR-074K7L" 0603 1510.5,347 r180 top value=4.7k
R17 "RC0402JR-070RL" 0402 1676.38,1218 r90 top value=0
R18 "RC0603JR-0710KL" 0603 1295,727 r270 top value=2.2k
R19 "CRCW0402270RJNED" 0402 1516,830.5 r180 top value=270
R20 "RC0402JR-070RL" 0402 890.04,1838 r0 top value=0
R21 "RC0603JR-0710KL" 0603 1593,727 r270 top value=2.2k
R22 "RC0402JR-070RL" 0402 699,1656.63 r90 top value=0
R23 "RC0402JR-070RL" 0402 1315.24,2058.54 r270 top value=0
R24 "CRCW04021K00JNED" 0402 1086.37,3626 r0 top value=1.0k
R25 "CRCW04021K00JNED" 0402 1086.37,3574 r0 top value=1.0k
R26 "CRCW04021K00JNED" 0402 1086,3522 r0 top value=1.0k
R27 "CRCW04021K00JNED" 0402 1086.37,3470 r0 top value=1.0k
R28 "CRCW0402100RJNED" 0402 231,3720 r0 top value=100
R29 "CRCW0402470RJNED" 0402 239,2815 r0 top value=470
R30 "CRCW0402470RJNED" 0402 239,2734 r0 top value=470
R31 "CRCW040210K0JNED" 0402 774,3749 r90 top value=10k
R32 "CRCW04024K87FKED" 0402 1086,3418 r180 top value=4.87k
R33 "CRCW0402100RJNED" 0402 718.87,3749 r270 top value=100
R34 "CRCW04021K00JNED" 0402 580.4,2889.63 r270 top value=1.0k
R35 "CRCW040251R0JNED" 0402 1085.38,3730 r0 top value=51
R36 "RC0402FR-07220KL" 0402 1717,3400 r270 top value=220k
R37 "RC0402FR-07220KL" 0402 1717,3519.62 r270 top value=220k
R38 "ERJ-2RKF3301X" 0402 1907,3484 r0 top value=3.30k
R39 "CRCW04022K20FKED" 0402 1906.38,3594.2 r0 top value=2.20k
R40 "CRCW04026K81FKED" 0402 1906.38,3539 r0 top value=6.81k
R41 "CRCW04024K70JNED" 0402 1613,3401 r270 top value=4.7k
R42 "CRCW04024K70JNED" 0402 1551,3400.35 r270 top value=4.7k
R43 "RC0402FR-07220KL" 0402 1452,3326 r0 top value=220k
R44 "RC0402FR-07220KL" 0402 1452,3379 r0 top value=220k
R45 "RC0402FR-0747KL" 0402 1452,3271 r180 top value=47.0k
R46 "RC0402FR-0747KL" 0402 1452,3163 r0 top value=47.0k
R47 "RC0402FR-07820RL" 0402 1907,3791 r180 top value=820
R48 "CRCW0402470RJNED" 0402 2189,3726 r0 top value=470
R49 "RC0402FR-0747KL" 0402 1908.38,3323 r0 top value=47.0k
R50 "RC0402FR-07220KL" 0402 1908,3214 r0 top value=220k
R51 "RC0402FR-07220KL" 0402 231.62,3054 r180 top value=220k
R52 "RC0603JR-070RL" 0603 1907,3655.41 r0 top value=0
R53 "RC0402FR-07220KL" 0402 1907.62,3268 r180 top value=220k
R54 "RC0402FR-07220KL" 0402 231,3107 r0 top value=220k
R55 "RC0603JR-070RL" 0603 1556.69,2183.75 r0 top value=0
R56 "ERA3ARB103V" ERA3A 551,937.75 r270 top value=10.0k
R57 "RC0603JR-070RL" 0603 674.99,932 r180 top value=0
R58 "RC0603JR-070RL" 0603 627,1645.31 r270 top value=0
R59 "CRCW04024K70JNED" 0402 1590,1356.35 r180 top value=4.7k
R60 "CRCW04024K70JNED" 0402 1590.38,1411.04 r180 top value=4.7k
R61 "RC0603JR-070RL" 0603 674.99,1003.04 r180 top value=0
R62 "RC0603JR-070RL" 0603 1862.84,960.25 r90 top value=0
R63 "RC0603JR-070RL" 0603 1790.84,960.25 r90 top value=0
R64 "RC0603JR-070RL" 0603 1650.84,961.25 r90 top value=0
R65 "RC0603JR-070RL" 0603 1721.84,960.75 r90 top value=0
R66 "RC0603JR-070RL" 0603 882,1511 r0 top value=0
R67 "RC0603JR-070RL" 0603 883,1580 r0 top value=0
R68 "RC0603JR-070RL" 0603 547.5,433.99 r180 top value=0
R69 "RC0603JR-070RL" 0603 547.5,503.99 r0 top value=0
R70 "RC0603JR-070RL" 0603 98.51,457.99 r0 top value=0
R71 "RC0603JR-070RL" 0603 98.51,527.99 r180 top value=0
R72 "RC0603FR-07100RL" 0603 547.5,573.99 r0 top value=100
R73 "RC0603JR-070RL" 0603 309.01,655.99 r0 top value=0
R74 "RC0603JR-070RL" 0603 549,349 r0 top value=0
R75 "RC0603JR-070RL" 0603 1240,2200 r270 top value=0
R76 "RC0603JR-070RL" 0603 1250,2050 r270 top value=0
R77 "RC0603JR-070RL" 0603 1100,2200 r270 top value=0
R78 "RC0603JR-070RL" 0603 1140,2050 r270 top value=0
R79 "RC0603JR-070RL" 0603 820,2200 r270 top value=0
R80 "RC0603JR-070RL" 0603 920,2050 r270 top value=0
R81 "RC0603JR-070RL" 0603 1380,2200 r270 top value=0
R82 "RC0603JR-070RL" 0603 1379.84,2050.75 r270 top value=0
R83 "RC0603JR-070RL" 0603 960,2200 r270 top value=0
R84 "RC0603JR-070RL" 0603 1030,2050 r270 top value=0
R85 "ERJ-2RKF3301X" 0402 1087,3207 r0 top value=3.30k
R86 "RC0603JR-070RL" 0603 694.94,3912.96 r0 top value=0
R87 "RC0402FR-07330KL" 0402 231,2947 r0 top value=330k
R88 "RC0402FR-07220KL" 0402 231,3000 r0 top value=220k
R89 "RC0603JR-070RL" 0603 260,3930.72 r90 top value=0
R90 "CRCW04021M00FKED" 0402 704.38,3994 r180 top value=1.00Meg
R91 "CRCW040210K0JNED" 0402 142,3670.76 r90 top value=10k
R92 "CRCW040210K0JNED" 0402 142,3557.38 r90 top value=10k
RT1 "TMP6131DECT" DEC0002A 550,1064.5 r270 top
S1 "1188E-1K2-V-TR" SW_1188E 106.78,2434.72 r0 top locked
S2 "1188E-1K2-V-TR" SW_1188E 2193,2434 r180 top locked
S3 "1188E-1K2-V-TR" SW_1188E 1835,4091 r270 top locked
SH-J1 "SNT-100-BK-G" SNT-100-BK-G 454.21,2635 r90 top value="J101: 1-2"
SH-J2 "SNT-100-BK-G" SNT-100-BK-G 554.21,2635 r90 top value="J101: 3-4"
SH-J3 "SNT-100-BK-G" SNT-100-BK-G 654.21,2635 r90 top value="J101: 5-6"
SH-J4 "SNT-100-BK-G" SNT-100-BK-G 754.21,2635 r90 top value="J101: 7-8"
SH-J5 "SNT-100-BK-G" SNT-100-BK-G 854.21,2635 r90 top value="J101: 9-10"
SH-J6 "SNT-100-BK-G" SNT-100-BK-G 954.21,2635 r90 top value="J101: 11-12"
SH-J7 "SNT-100-BK-G" SNT-100-BK-G 1054.21,2635 r90 top value="J101: 12-13"
SH-J8 "SNT-100-BK-G" SNT-100-BK-G 1154.21,2635 r90 top value="J101: 15-16"
SH-J9 "SNT-100-BK-G" SNT-100-BK-G 1254.21,2635 r90 top value="J101: 17-18"
SH-J10 "SNT-100-BK-G" SNT-100-BK-G 667,1999 r90 top value="J14: 1-2"
SH-J11 "SNT-100-BK-G" SNT-100-BK-G 1708.97,591.06 r90 top value="J1: 1-2"
SH-J12 "SNT-100-BK-G" SNT-100-BK-G 1808.97,591.06 r90 top value="J2: 1-2"
SH-J13 "SNT-100-BK-G" SNT-100-BK-G 1908.97,591.06 r90 top value="J3: 1-2"
SH-J14 "SNT-100-BK-G" SNT-100-BK-G 1184.79,586.37 r90 top value="J4: 1-2"
SH-J15 "SNT-100-BK-G" SNT-100-BK-G 820,588 r90 top value="J5: 1-2"
SH-J16 "SNT-100-BK-G" SNT-100-BK-G 920,588 r90 top value="J6: 1-2"
SH-J17 "SNT-100-BK-G" SNT-100-BK-G 1020,588 r90 top value="J7: 1-2"
SH-J18 "SNT-100-BK-G" SNT-100-BK-G 322,2468.97 r90 top value="J8: 1-2"
SH-J19 "SNT-100-BK-G" SNT-100-BK-G 1346.21,540 r180 top value="J9: 2"
SH-J20 "SNT-100-BK-G" SNT-100-BK-G 1549.35,541 r180 top value="J12: 2"
SH-J21 "SNT-100-BK-G" SNT-100-BK-G 670,1400 r90 top value="J15: 1-2"
SH-J22 "SNT-100-BK-G" SNT-100-BK-G 1565.39,1999 r90 top value="J25: 1-2"
SH-J23 "SNT-100-BK-G" SNT-100-BK-G 1682,1999 r90 top value="J26: 1-2"
SH-J24 "SNT-100-BK-G" SNT-100-BK-G 370,1000 r90 top value="J27: 1-2"
SH-J25 "SNT-100-BK-G" SNT-100-BK-G 1069.38,1033.52 r90 top value="J13: 1-2"
T1 "DMG1013UW-7" SOT-323 2191.4,3623.41 r0 top value=-20V
T2 "BC850CW,115" SOT-323 2034,3649 r0 top value="45 V"
TP1 "5001" Keystone5001 1601,3246 r90 top
TP2 "5001" Keystone5001 1601,3046 r90 top
TP3 "5001" Keystone5001 1601,3146 r90 top
TP4 "5001" Keystone5001 50,3835 r90 top
TP5 "5001" Keystone5001 50,3735 r90 top
TP6 "5001" Keystone5001 50,3635 r90 top
TP7 "5001" Keystone5001 50,3535 r90 top
TP8 "5001" Keystone5001 50,3435 r90 top
TP9 "5001" Keystone5001 50,3335 r90 top
TP10 "5001" Keystone5001 50,3235 r90 top
U1 "TPD6E004RSER" RSE0008A 1517.93,2513.49 r180 top
U2 "LM4040C25IDCKR" DCK0005A_N 792.34,2845.16 r180 top
U2 "OPA2365AIDR" D0008A_L 322.66,488.99 r0 top
USB2 "1051640001" Molex_1051640001 450.09,4160.09 r180 top locked
XDS1 "MSP432E401YTPDTR" PDT0128A 648,3328 r90 top (schematic designator MSP1)
XDS2 "MSP430G2452IRSA16R" RSA0016B 1557,3603 r0 top (schematic designator MSP2)
Y1 "X1A0001410014" Epson_FC-135 1294.19,1231 r180 top
Y2 "FA-238 48.0000MB-W0" Epson_FA-238 1491.35,1212 r270 top
Y3 "NX3225GA-16.000M-STD-CRG-1" NDK_NX3225GA 555,3743 r90 top
ZZ2 "These assemblies must be clean and free from flux and all contaminants. Use of no clean flux is not acceptable." AssemblyNote 145,5140 r0 top
ZZ3 "These assemblies must comply with workmanship standards IPC-A-610 Class 2, unless otherwise specified." AssemblyNote 140,5250 r0 top
ZZ4 "Place a click-in Standoff (MAE-10, KangYang)  in hole MH1/MH2" AssemblyNote 135,5345 r0 top

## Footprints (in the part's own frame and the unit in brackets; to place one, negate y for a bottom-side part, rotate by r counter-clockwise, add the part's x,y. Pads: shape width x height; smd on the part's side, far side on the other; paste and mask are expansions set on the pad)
19-337_RGB [mm] "SMD, 6-Leads, Body 1.6x1.6mm"
  rect 0.55x0.4 smd: 1(-0.675,0.725) 3(-0.675,-0.725) 4(0.675,0.725) 6(0.675,-0.725)
  rect 0.7x0.5 smd: 2(-0.75,0) 5(0.75,0)
  silkscreen extent -1.2,0.6 -1.2,0.9, body extent -0.85,-0.85 0.85,0.85, height 0.35
0402 [mm] "0402 from SM-752 data"
  rect 0.8x0.6 smd: 1(-0.6,0) 2(0.6,0)
  silkscreen extent -1.22,-0.52 1.22,0.52, body extent -0.55,-0.3 0.55,0.3, height 0.6
0603 [mm] "0603 from SM-752 data"
  rect 1x0.95 smd: 1(-0.8,0) 2(0.8,0)
  silkscreen extent -1.52,-0.69 1.52,0.69, body extent -0.87,-0.47 0.87,0.47, height 1
1111C_Red [mm] "SMD, 2-Leads, Body 1.6x0.8mm"
  rect 0.8x0.8 smd: 1(-0.8,0) 2(0.8,0)
  silkscreen extent -1,-0.7 1.7,0.7, body extent -0.85,-0.45 0.85,0.45, height 0.8
3216-18 [mm] "Based on AVX recommendation in http://www.avx.com/download/software/literature/AVX-Footprint-Library.pdf"
  rrect7% 1.4x1.8 smd: 1(-1.3,0) 2(1.3,0)
  silkscreen extent -1.9,-1.12 0.8,1.12, body extent -1.7,-0.9 1.7,0.9, height 1.82
AssemblyNote [mil] "Assembly Note"
BoosterPack_40pin_J1J3 [mm] "Receptacle, 2.54mm, 10x2, TH"
  rrect6% 1.55x1.55 hole 1.02: 1(1.27,11.43)
  round 1.55 hole 1.02: 2(1.27,8.89) 3(1.27,6.35) 4(1.27,3.81) 5(1.27,1.27) 6(1.27,-1.27) 7(1.27,-3.81) 8(1.27,-6.35) 9(1.27,-8.89) 10(1.27,-11.43) 21(-1.27,11.43) 22(-1.27,8.89) 23(-1.27,6.35) 24(-1.27,3.81) 25(-1.27,1.27) 26(-1.27,-1.27) 27(-1.27,-3.81) 28(-1.27,-6.35) 29(-1.27,-8.89) 30(-1.27,-11.43)
  silkscreen extent -7.62,-12.95 7.62,12.95, body extent -2.48,-12.95 2.48,12.95, height 8.51
BoosterPack_40pin_J2J4 [mm] "Receptacle, 2.54mm, 10x2, TH"
  round 1.55 hole 1.02: 11(-1.27,-11.43) 12(-1.27,-8.89) 13(-1.27,-6.35) 14(-1.27,-3.81) 15(-1.27,-1.27) 16(-1.27,1.27) 17(-1.27,3.81) 18(-1.27,6.35) 19(-1.27,8.89) 20(-1.27,11.43) 31(1.27,-11.43) 32(1.27,-8.89) 33(1.27,-6.35) 34(1.27,-3.81) 35(1.27,-1.27) 36(1.27,1.27) 37(1.27,3.81) 38(1.27,6.35) 39(1.27,8.89) 40(1.27,11.43)
  silkscreen extent -7.62,-12.95 2.48,12.95, body extent -2.48,-12.95 2.48,12.95, height 8.51
CBC2518 [mm] "Taiyo Yuden"
  rect 0.6x2 smd: 1(-1.05,0) 2(1.05,0)
  silkscreen extent -0.45,-1.1 0.45,1.1, body extent -1.35,-1 1.35,1, height 2
CE_Mark_5mm [mil] "Minimum text height for CE Mark"
  silkscreen extent -138,-98 138,98
CONN_90120-0122 [mm] "Molex"
  rect 1.65x1.65 hole 1.016 mask+0: 1(-1.27,0)
  round 1.65 hole 1.016 mask+0: 2(1.27,0)
  silkscreen extent -3.56,-1.27 2.54,1.27, body extent -2.54,-1.27 2.54,1.27, height 9.29
CONN_PEC03SAAN [mm] "SULLINS"
  rect 1.5x1.5 hole 1.016: 1(-2.54,0)
  round 1.5 hole 1.016: 2(0,0) 3(2.54,0)
  silkscreen extent -4.72,-1.27 3.81,1.27, body extent -3.84,-1.3 3.84,1.3, height 8.38
D0008A_L [mm] "SOIC, 8-Leads, Body 4.9x3.9mm, Pitch 1.27mm, IPC High Density"
  oval 1.25x0.55 smd: 1(-2.625,1.905) 2(-2.625,0.635) 3(-2.625,-0.635) 4(-2.625,-1.905) 5(2.625,-1.905) 6(2.625,-0.635) 7(2.625,0.635) 8(2.625,1.905)
  silkscreen extent -3.1,-2.5 0.9,2.5, body extent -3,-2.45 3,2.45, height 1.63
DBV0005A_N [mm] "SOT23, 5-Leads, Body 2.9x1.6mm, Pitch 0.95mm, Lead Span 2.8mm, IPC Medium Density"
  rrect17% 1x0.6 smd: 1(-1.375,0.95) 2(-1.375,0) 3(-1.375,-0.95) 4(1.375,-0.95) 5(1.375,0.95)
  silkscreen extent -0.25,-1.55 0.25,1.55, body extent -1.42,-1.46 1.42,1.46, height 1.09
DCK0005A_N [mm] "SOT353, 5-Leads, Body 2x1.3mm, Pitch 0.65mm, Lead Span 2.1mm, IPC Medium Density"
  rrect25% 0.85x0.4 smd: 1(-1.125,0.65) 2(-1.125,0) 3(-1.125,-0.65) 4(1.125,-0.65) 5(1.125,0.65)
  silkscreen extent -1.48,-1.02 0.55,1.1, body extent -1.14,-1 1.14,1, height 0.95
DEC0002A [mm] "X1SON-2"
  rrect57% 0.35x0.6 smd paste-0.5 mask-0.05: 1(-0.325,0) 2(0.325,0)
  rrect33% 0.3x0.5 on Top Paste: 1S(-0.35,0) 2S(0.35,0)
  body extent -0.5,-0.3 0.5,0.3, height 0.5
DRB0008A [mm] "VSON-8"
  rrect32% 0.6x0.31 smd: 1(-1.4,0.975) 2(-1.4,0.325) 3(-1.4,-0.325) 4(-1.4,-0.975) 5(1.4,-0.975) 6(1.4,-0.325) 7(1.4,0.325) 8(1.4,0.975)
  rrect7% 1.5x1.75 smd paste-0.75: 9(0,0)
  Top Layer region: -0.7,-0.875 -0.49,-0.875 -0.471,-0.879 -0.455,-0.89 -0.444,-0.906 -0.44,-0.925 -0.44,-0.925 -0.44,-1.65 -0.436,-1.669 -0.425,-1.685 -0.409,-1.696 -0.39,-1.7 -0.39,-1.7 -0.26,-1.7 -0.241,-1.696 -0.225,-1.685 -0.214,-1.669 -0.21,-1.65 -0.21,-1.65 -0.21,-0.925 -0.206,-0.906 -0.195,-0.89 -0.179,-0.879 -0.16,-0.875 -0.16,-0.875 0.16,-0.875 0.179,-0.879 0.195,-0.89 0.206,-0.906 0.21,-0.925 0.21,-0.925 0.21,-1.65 0.21,-1.65 0.214,-1.669 0.225,-1.685 0.241,-1.696 0.26,-1.7 0.26,-1.7 0.39,-1.7 0.409,-1.696 0.425,-1.685 0.436,-1.669 0.44,-1.65 0.44,-1.65 0.44,-0.925 0.444,-0.906 0.455,-0.89 0.471,-0.879 0.49,-0.875 0.49,-0.875 0.7,-0.875 0.719,-0.871 0.735,-0.86 0.746,-0.844 0.75,-0.825 0.75,-0.825 0.75,0.825 0.746,0.844 0.735,0.86 0.719,0.871 0.7,0.875 0.7,0.875 0.49,0.875 0.471,0.879 0.455,0.89 0.444,0.906 0.44,0.925 0.44,0.925 0.44,1.65 0.436,1.669 0.425,1.685 0.409,1.696 0.39,1.7 0.39,1.7 0.26,1.7 0.241,1.696 0.225,1.685 0.214,1.669 0.21,1.65 0.21,1.65 0.21,1.65 0.21,0.925 0.206,0.906 0.195,0.89 0.179,0.879 0.16,0.875 0.16,0.875 -0.16,0.875 -0.179,0.879 -0.195,0.89 -0.206,0.906 -0.21,0.925 -0.21,0.925 -0.21,1.65 -0.214,1.669 -0.225,1.685 -0.241,1.696 -0.26,1.7 -0.26,1.7 -0.39,1.7 -0.409,1.696 -0.425,1.685 -0.436,1.669 -0.44,1.65 -0.44,1.65 -0.44,0.925 -0.444,0.906 -0.455,0.89 -0.471,0.879 -0.49,0.875 -0.49,0.875 -0.7,0.875 -0.719,0.871 -0.735,0.86 -0.746,0.844 -0.75,0.825 -0.75,0.825 -0.75,-0.825 -0.746,-0.844 -0.735,-0.86 -0.719,-0.871 -0.7,-0.875
  silkscreen extent -1.73,-1.73 1.73,1.73, body extent -1.5,-1.5 1.5,1.5, height 0.77
DRY0006A [mm] "PSON, 6-Leads, Body 1x1.45mm, Pitch 0.5mm, TI Recommended"
  rect 0.35x0.2 smd: 1(-0.275,0.5)
  rect 0.3x0.2 smd: 2(-0.3,0) 3(-0.3,-0.5) 4(0.3,-0.5) 5(0.3,0) 6(0.3,0.5)
  silkscreen extent -0.5,-0.85 0.2,0.85, body extent -0.53,-0.75 0.53,0.75, height 0.61
Epson_FA-238 [mm] "SMD, 4-Leads, Body 3.2x2.5mm"
  rrect8% 1.2x1.4 smd: 1(-0.8,1.1) 2(-0.8,-1.1) 3(0.8,-1.1) 4(0.8,1.1)
  silkscreen extent -1.65,-2.05 1.65,2.05, body extent -1.3,-1.65 1.3,1.65, height 0.7
Epson_FC-135 [mm] "SMD, 2-Leads, Body 3.2x1.5mm"
  rect 1x1.8 smd: 1(-1.25,0) 2(1.25,0)
  silkscreen extent -0.35,-0.8 0.35,0.8, body extent -1.65,-0.8 1.65,0.8, height 0.9
ERA3A [mm] "SMD, 2-Leads, Body 1.6x0.8mm"
  rrect15% 0.65x0.9 smd: 1(-0.725,0) 2(0.725,0)
  body extent -0.9,-0.5 0.9,0.5, height 0.55
ESD_Overlay_Large [mil]
  silkscreen extent -254,-219 250,219
FCC_disclaimer [mil]
Fiducial10-30 [mm]
  round 1 smd mask+1: 1(0,0)
  Top Layer keep-out circle w1.678: c0,0 r0.75
FP-ERA-2AEB104X_0402-MFG [mm]
  rrect21% 0.475x0.5 smd paste+0 mask+0: 1(-0.512,0) 2(0.512,0)
  silkscreen extent -0.5,-0.63 0.5,0.63, body extent -0.85,-0.4 0.85,0.4, height 0.25
FP-VEMD4110X01_0805-MFG [mm]
  rrect17% 0.9x0.6 smd paste+0 mask+0: 1(0,-0.8)
  rrect11% 0.9x1.3 smd paste+0 mask+0: 2(0,0.45)
  silkscreen extent -0.85,-1.78 0.85,1.05, body extent -0.77,-1.2 0.77,1.2, height 0.25
Keystone5001 [mil] "For Keystone 500x miniature loop terminals"
  round 80 hole 40: 1(0,0)
  silkscreen extent -52,-52 52,52, body extent -49,-49 49,49, height 182
KY_MAE-10 [mil] "Spacer Nylon Support"
  body extent -125,-108 125,108, height 394
LED_LTST-C190 [mm] "Lite-On"
  rect 0.8x0.8 smd: 1(-0.75,0) 2(0.75,0)
  silkscreen extent -1.1,-0.8 1.8,0.8, body extent -0.85,-0.45 0.85,0.45, height 0.9
Molex_1051640001 [mm] "Receptacle, USB 2.0, Micro B, 5 Pos, 0.65mm Pitch, R/A, SMT"
  rrect22% 0.45x1.38 smd: 1(1.3,4.11) 2(0.65,4.11) 3(0,4.11) 4(-0.65,4.11) 5(-1.3,4.11)
  rrect7% 1.475x2.1 smd: 6(-2.462,3.75) 11(2.462,3.75)
  rrect100% 1.4x2.1 hole 0.6 slot 1.3 at 90 deg: 7(-3.95,1.45) 10(3.95,1.45)
  rrect7% 1.375x1.9 smd: 8(-0.937,1.45) 9(0.937,1.45)
  silkscreen extent 1.2,5.1 1.4,5.4, body extent -4.1,-0.7 4.1,4.47, height 2.45
NDK_NX3225GA [mm] "NDK"
  rect 1.2x1.4 smd: 1(-0.8,1.1) 2(-0.8,-1.1) 3(0.8,-1.1) 4(0.8,1.1)
  silkscreen extent -1.9,-0.1 1.4,2, body extent -1.3,-1.65 1.3,1.65, height 0.9
NPTH125mil [mil]
  round 120 hole 125 unplated mask+15: 1(0,0)
PDT0128A [mm] "Thin QFP, 128-Leads, Body 14x14mm, Pitch 0.4mm"
  oval 1.4x0.2 smd: 1(-7.7,6.2) 2(-7.7,5.8) 3(-7.7,5.4) 4(-7.7,5) 5(-7.7,4.6) 6(-7.7,4.2) 7(-7.7,3.8) 8(-7.7,3.4) 9(-7.7,3) 10(-7.7,2.6) 11(-7.7,2.2) 12(-7.7,1.8) 13(-7.7,1.4) 14(-7.7,1) 15(-7.7,0.6) 16(-7.7,0.2) 17(-7.7,-0.2) 18(-7.7,-0.6) 19(-7.7,-1) 20(-7.7,-1.4) 21(-7.7,-1.8) 22(-7.7,-2.2) 23(-7.7,-2.6) 24(-7.7,-3) 25(-7.7,-3.4) 26(-7.7,-3.8) 27(-7.7,-4.2) 28(-7.7,-4.6) 29(-7.7,-5) 30(-7.7,-5.4) 31(-7.7,-5.8) 32(-7.7,-6.2) 65(7.7,-6.2) 66(7.7,-5.8) 67(7.7,-5.4) 68(7.7,-5) 69(7.7,-4.6) 70(7.7,-4.2) 71(7.7,-3.8) 72(7.7,-3.4) 73(7.7,-3) 74(7.7,-2.6) 75(7.7,-2.2) 76(7.7,-1.8) 77(7.7,-1.4) 78(7.7,-1) 79(7.7,-0.6) 80(7.7,-0.2) 81(7.7,0.2) 82(7.7,0.6) 83(7.7,1) 84(7.7,1.4) 85(7.7,1.8) 86(7.7,2.2) 87(7.7,2.6) 88(7.7,3) 89(7.7,3.4) 90(7.7,3.8) 91(7.7,4.2) 92(7.7,4.6) 93(7.7,5) 94(7.7,5.4) 95(7.7,5.8) 96(7.7,6.2)
  oval 0.2x1.4 smd: 33(-6.2,-7.7) 34(-5.8,-7.7) 35(-5.4,-7.7) 36(-5,-7.7) 37(-4.6,-7.7) 38(-4.2,-7.7) 39(-3.8,-7.7) 40(-3.4,-7.7) 41(-3,-7.7) 42(-2.6,-7.7) 43(-2.2,-7.7) 44(-1.8,-7.7) 45(-1.4,-7.7) 46(-1,-7.7) 47(-0.6,-7.7) 48(-0.2,-7.7) 49(0.2,-7.7) 50(0.6,-7.7) 51(1,-7.7) 52(1.4,-7.7) 53(1.8,-7.7) 54(2.2,-7.7) 55(2.6,-7.7) 56(3,-7.7) 57(3.4,-7.7) 58(3.8,-7.7) 59(4.2,-7.7) 60(4.6,-7.7) 61(5,-7.7) 62(5.4,-7.7) 63(5.8,-7.7) 64(6.2,-7.7) 97(6.2,7.7) 98(5.8,7.7) 99(5.4,7.7) 100(5,7.7) 101(4.6,7.7) 102(4.2,7.7) 103(3.8,7.7) 104(3.4,7.7) 105(3,7.7) 106(2.6,7.7) 107(2.2,7.7) 108(1.8,7.7) 109(1.4,7.7) 110(1,7.7) 111(0.6,7.7) 112(0.2,7.7) 113(-0.2,7.7) 114(-0.6,7.7) 115(-1,7.7) 116(-1.4,7.7) 117(-1.8,7.7) 118(-2.2,7.7) 119(-2.6,7.7) 120(-3,7.7) 121(-3.4,7.7) 122(-3.8,7.7) 123(-4.2,7.7) 124(-4.6,7.7) 125(-5,7.7) 126(-5.4,7.7) 127(-5.8,7.7) 128(-6.2,7.7)
  silkscreen extent -7.7,-6.3 6.3,6.99, body extent -8,-8 8,8, height 1.07
PEC03SAAN_Launchpad_3V3 [mm] "SULLINS"
  rect 1.65x1.65 hole 1.016: 1(-2.54,0)
  round 1.65 hole 1.016: 2(0,0) 3(2.54,0)
  silkscreen extent -3.81,-1.27 3.81,6.3, body extent -3.84,-1.3 3.84,1.3, height 8.38
PEC03SAAN_Launchpad_5V0 [mm] "SULLINS"
  rect 1.65x1.65 hole 1.016: 1(-2.54,0)
  round 1.65 hole 1.016: 2(0,0) 3(2.54,0)
  silkscreen extent -3.81,-6.31 3.81,1.27, body extent -3.84,-1.3 3.84,1.3, height 8.38
PM0064A-MFG [mm]
  rrect33% 1.5x0.3 smd paste+0 mask+0: 1(-5.7,3.75) 2(-5.7,3.25) 3(-5.7,2.75) 4(-5.7,2.25) 5(-5.7,1.75) 6(-5.7,1.25) 7(-5.7,0.75) 8(-5.7,0.25) 9(-5.7,-0.25) 10(-5.7,-0.75) 11(-5.7,-1.25) 12(-5.7,-1.75) 13(-5.7,-2.25) 14(-5.7,-2.75) 15(-5.7,-3.25) 16(-5.7,-3.75) 33(5.7,-3.75) 34(5.7,-3.25) 35(5.7,-2.75) 36(5.7,-2.25) 37(5.7,-1.75) 38(5.7,-1.25) 39(5.7,-0.75) 40(5.7,-0.25) 41(5.7,0.25) 42(5.7,0.75) 43(5.7,1.25) 44(5.7,1.75) 45(5.7,2.25) 46(5.7,2.75) 47(5.7,3.25) 48(5.7,3.75)
  rrect33% 0.3x1.5 smd paste+0 mask+0: 17(-3.75,-5.7) 18(-3.25,-5.7) 19(-2.75,-5.7) 20(-2.25,-5.7) 21(-1.75,-5.7) 22(-1.25,-5.7) 23(-0.75,-5.7) 24(-0.25,-5.7) 25(0.25,-5.7) 26(0.75,-5.7) 27(1.25,-5.7) 28(1.75,-5.7) 29(2.25,-5.7) 30(2.75,-5.7) 31(3.25,-5.7) 32(3.75,-5.7) 49(3.75,5.7) 50(3.25,5.7) 51(2.75,5.7) 52(2.25,5.7) 53(1.75,5.7) 54(1.25,5.7) 55(0.75,5.7) 56(0.25,5.7) 57(-0.25,5.7) 58(-0.75,5.7) 59(-1.25,5.7) 60(-1.75,5.7) 61(-2.25,5.7) 62(-2.75,5.7) 63(-3.25,5.7) 64(-3.75,5.7)
  silkscreen extent -7.12,-5.1 5.1,5.1, body extent -6.55,-6.55 6.55,6.55, height 0.25
RSA0016B [mm] "QFN, 16-Leads, Body 4x4mm, Pitch 0.65mm, Thermal Pad 2.7x2.7mm, TI Recommended"
  oval 0.6x0.3 smd: 1(-1.9,0.975) 2(-1.9,0.325) 3(-1.9,-0.325) 4(-1.9,-0.975) 9(1.9,-0.975) 10(1.9,-0.325) 11(1.9,0.325) 12(1.9,0.975)
  oval 0.3x0.6 smd: 5(-0.975,-1.9) 6(-0.325,-1.9) 7(0.325,-1.9) 8(0.975,-1.9) 13(0.975,1.9) 14(0.325,1.9) 15(-0.325,1.9) 16(-0.975,1.9)
  rect 2.7x2.7 smd paste-1.35: 17(0,0)
  Top Layer keep-out region: -2,1.5 -1.5,1.5 -1.5,2 -2,2
  silkscreen extent -2.2,-2.2 2.2,2.2, body extent -2.05,-2.05 2.05,2.05, height 1.01
RSE0008A [mm] "QFN, 8-Leads, Body 1.5x1.5mm, Pitch 0.5mm, TI Recommended"
  rrect40% 0.55x0.25 smd: 1(-0.675,0.5) 3(-0.675,-0.5) 5(0.675,-0.5) 7(0.675,0.5)
  rrect50% 0.55x0.2 smd: 2(-0.675,0) 6(0.675,0)
  rrect33% 0.3x0.6 smd: 4(0,-0.65) 8(0,0.65)
  silkscreen extent -1.02,-0.92 0.77,0.93, body extent -0.75,-0.75 0.75,0.75, height 0.6
Samtec_FTSH-105-01-x-DV-K [mm] "Header(Shrouded), 1.27mm, 5x2, SMT"
  rect 2.79x0.74 smd: 1(-2.035,2.54) 2(2.035,2.54) 3(-2.035,1.27) 4(2.035,1.27) 5(-2.035,0) 6(2.035,0) 7(-2.035,-1.27) 8(2.035,-1.27) 9(-2.035,-2.54) 10(2.035,-2.54)
  silkscreen extent -3.73,-3.48 3.73,3.48, body extent -2.92,-3.18 2.92,3.17, height 6.13
Samtec_HTSW-105-07-G-S [mm] "Samtec 100mil, 1x5, 230 mil above insulator"
  rrect6% 1.65x1.65 hole 1.016: 1(-5.08,0)
  round 1.65 hole 1.016: 2(-2.54,0) 3(0,0) 4(2.54,0) 5(5.08,0)
  silkscreen extent -7.11,-1.27 6.35,1.27, body extent -6.35,-1.27 6.35,1.27, height 8.38
SNT-100-BK-G [mil] "Samtec STEP model"
  round 1 on Mech3: 0(0,0)
  body extent -100,-50 100,50, height 344
SOT-323 [mm] "Diodes Inc recommended land pattern.  2016-02-24"
  rrect21% 0.6x0.47 smd: 1(-0.95,0.65) 2(-0.95,-0.65) 3(0.95,0)
  silkscreen extent -1.14,-1.22 0.77,1.22, body extent -1.13,-1.13 1.12,1.12, height 1.13
Sullins_PBC03DAAN [mm] "Sullins 100mil, 2x3, 230 mil above insulator"
  rect 1.65x1.65 hole 1.016: 1(-1.27,2.54)
  round 1.65 hole 1.016: 2(1.27,2.54) 3(-1.27,0) 4(1.27,0) 5(-1.27,-2.54) 6(1.27,-2.54)
  silkscreen extent -2.67,-3.81 2.54,4.58, body extent -2.54,-3.81 2.54,3.81, height 8.38
Sullins_PxC09DAAN [mm] "Header, 2.54mm, 9x2, TH"
  rrect50% 1.55x1.55 hole 1.02: 1(-1.27,-10.16)
  round 1.55 hole 1.02: 2(1.27,-10.16) 3(-1.27,-7.62) 4(1.27,-7.62) 5(-1.27,-5.08) 6(1.27,-5.08) 7(-1.27,-2.54) 8(1.27,-2.54) 9(-1.27,0) 10(1.27,0) 11(-1.27,2.54) 12(1.27,2.54) 13(-1.27,5.08) 14(1.27,5.08) 15(-1.27,7.62) 16(1.27,7.62) 17(-1.27,10.16) 18(1.27,10.16)
  silkscreen extent -2.95,-11.43 2.54,11.43, body extent -2.54,-11.43 2.54,11.43, height 8.38
SW_1188E [mm] "SMD, 4-Leads, Body 7.8x3.5mm"
  rrect10% 1x1.45 smd: 1(-1.1,3.375) 2(-1.1,-3.375)
  rrect11% 1.3x0.9 smd: 3(0.7,2.1) 4(0.7,-2.1)
  round 0 hole 0.9 unplated: ""(-0.35,-1.15) ""(-0.35,1.15)
  silkscreen extent -1.97,-2.28 0.95,2.28, body extent -2.55,-3.9 1.05,3.9, height 3.5
TE_5-1814832-1 [mm] "SMA Straight PCB Socket Die Cast, TH"
  round 2 hole 1.5: 1(0,0)
  round 2.1 hole 1.6: 2(-2.54,2.54) 3(-2.54,-2.54) 4(2.54,-2.54) 5(2.54,2.54)
  silkscreen extent -3.2,-3.2 3.2,3.2, body extent -3.2,-3.2 3.2,3.2, height 9.5
TI_Horizontal_Overlay_Medium [mil]
  silkscreen extent -750,-93 750,94
TI_Horizontal_Overlay_Small [mil]
  silkscreen extent -545,-68 545,67
WEEE_Minimum [mil] "WEEElie bin"
  silkscreen extent -95,-172 99,104
WURTH_61301021121 [mm] "Header, 2.54mm, 5x2, TH"
  rrect25% 1.65x1.65 hole 1.15: 1(-5.08,-1.27)
  round 1.65 hole 1.15: 2(-5.08,1.27) 3(-2.54,-1.27) 4(-2.54,1.27) 5(0,-1.27) 6(0,1.27) 7(2.54,-1.27) 8(2.54,1.27) 9(5.08,-1.27) 10(5.08,1.27)
  silkscreen extent -6.35,-2.9 6.35,2.54, body extent -6.35,-2.54 6.35,2.54, height 8.54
